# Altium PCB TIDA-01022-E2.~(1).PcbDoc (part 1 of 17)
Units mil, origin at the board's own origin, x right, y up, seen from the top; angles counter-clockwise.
Board outline 6929.13 x 11614.17 mil, 12 copper layers (L1_Top Layer, L2_GND, L3_GND, L4_Signal Layer 1, L5_GND, L6_PWR, L7_GND/PWR, L8_PWR, L9_GND/PWR, L10_Signal Layer 2, L11_GND, L12_Bottom Layer), stack 64.6 mil thick; 1711 components, 1001 nets, 5985 pads, 3200 vias.
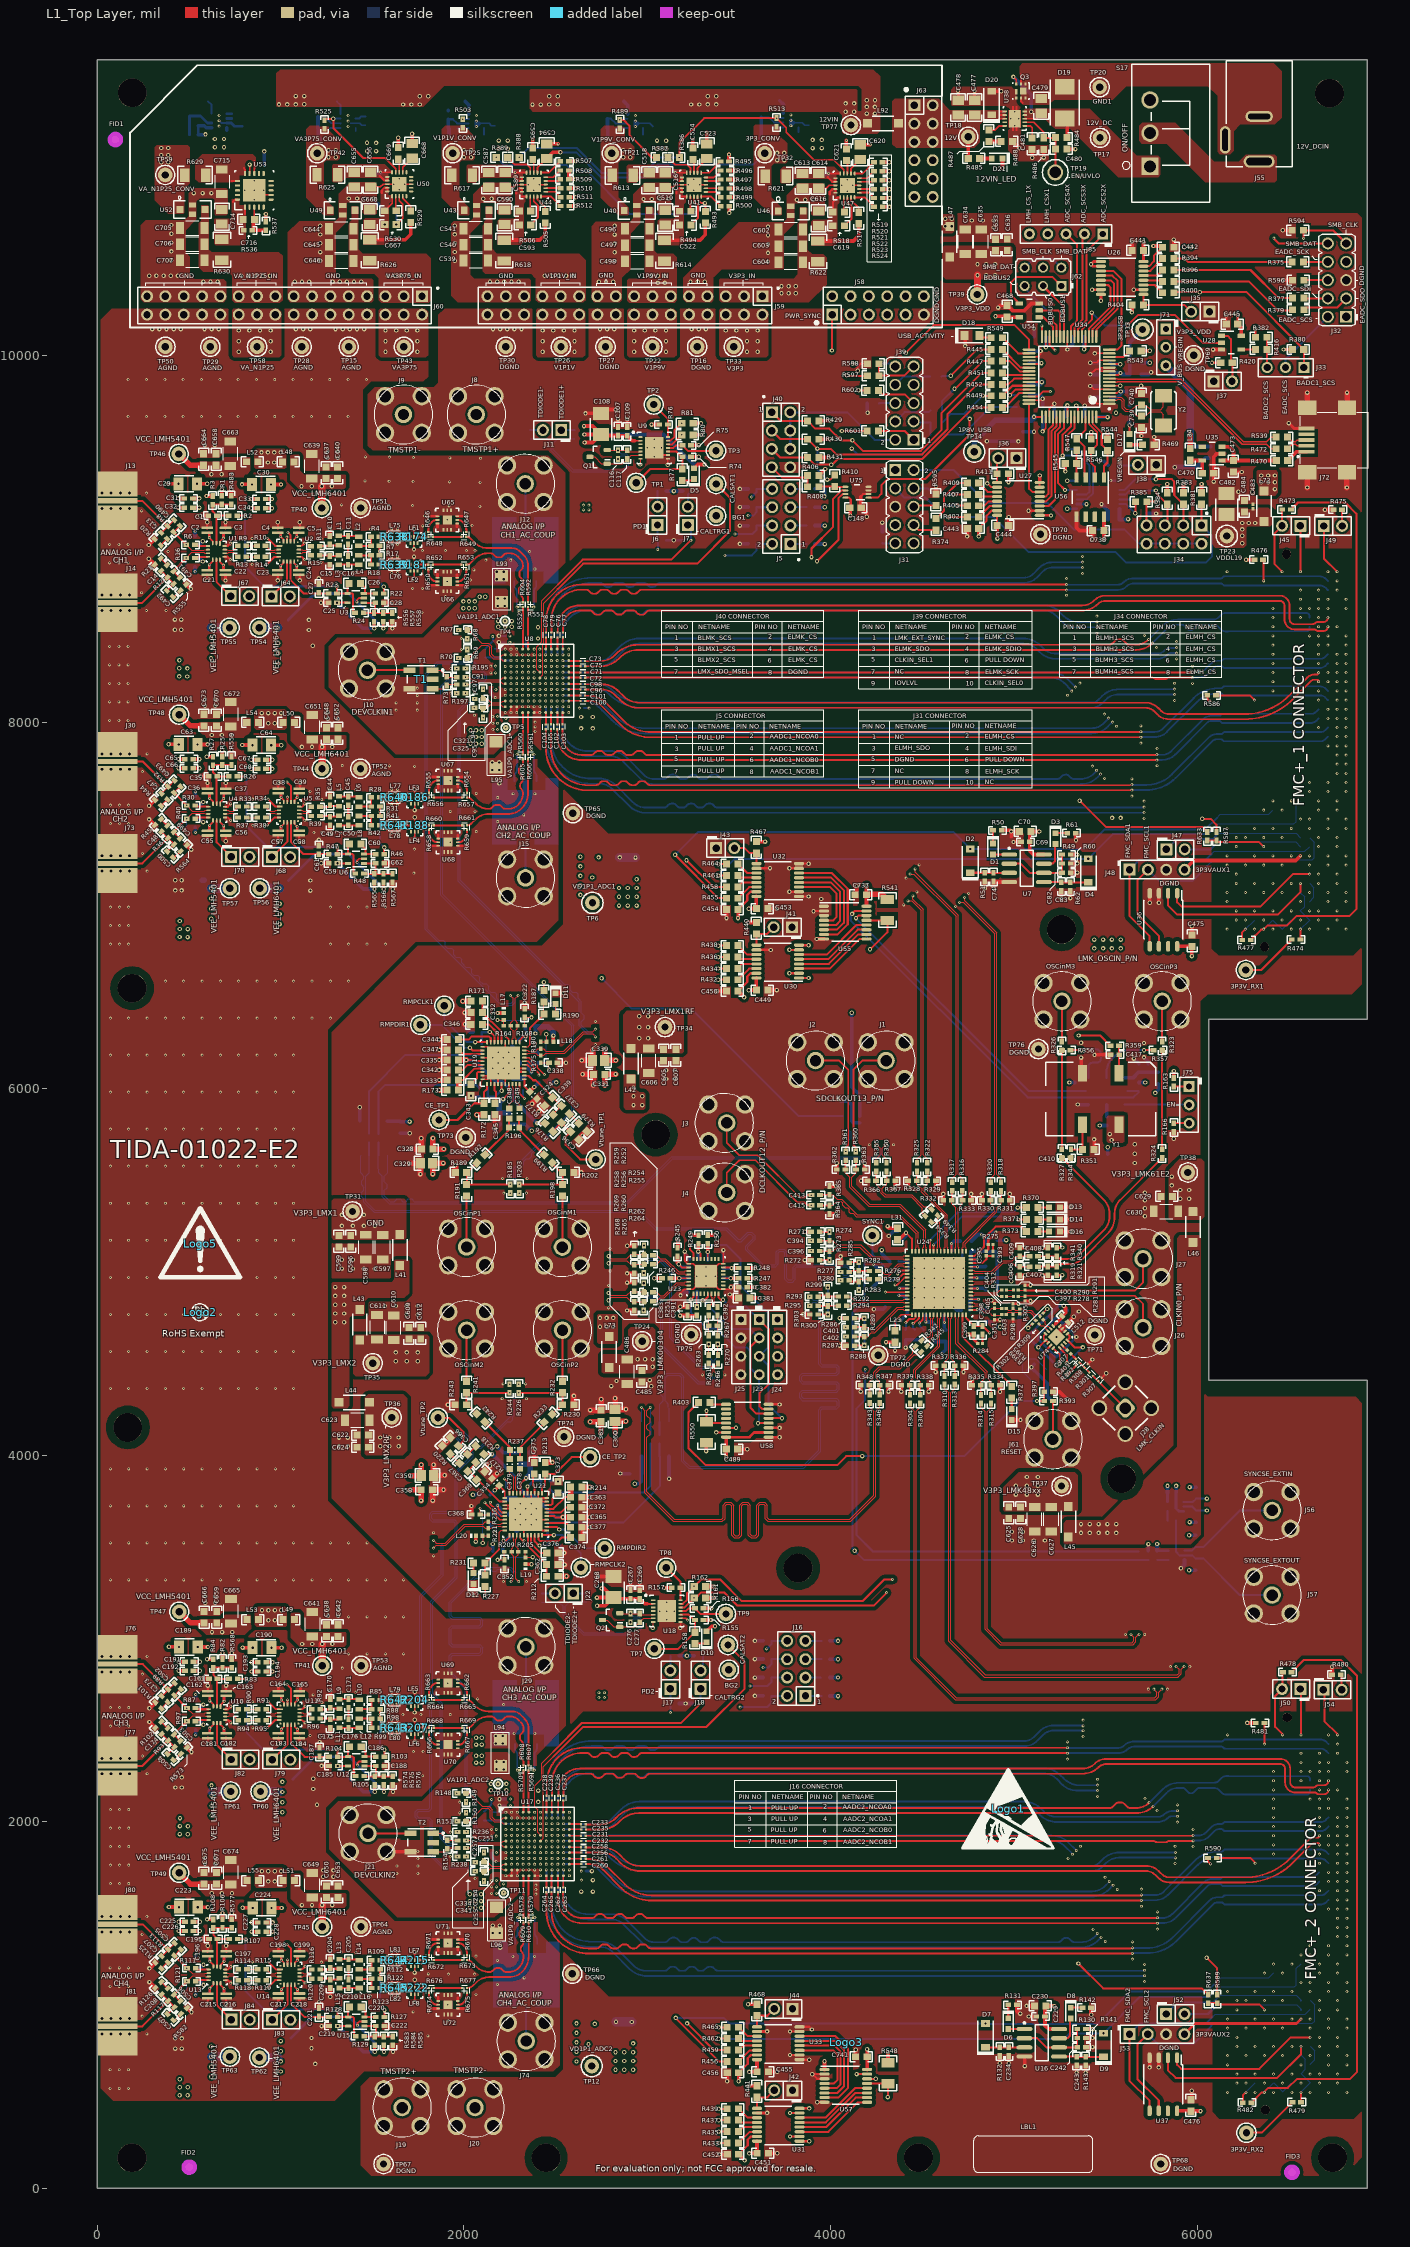
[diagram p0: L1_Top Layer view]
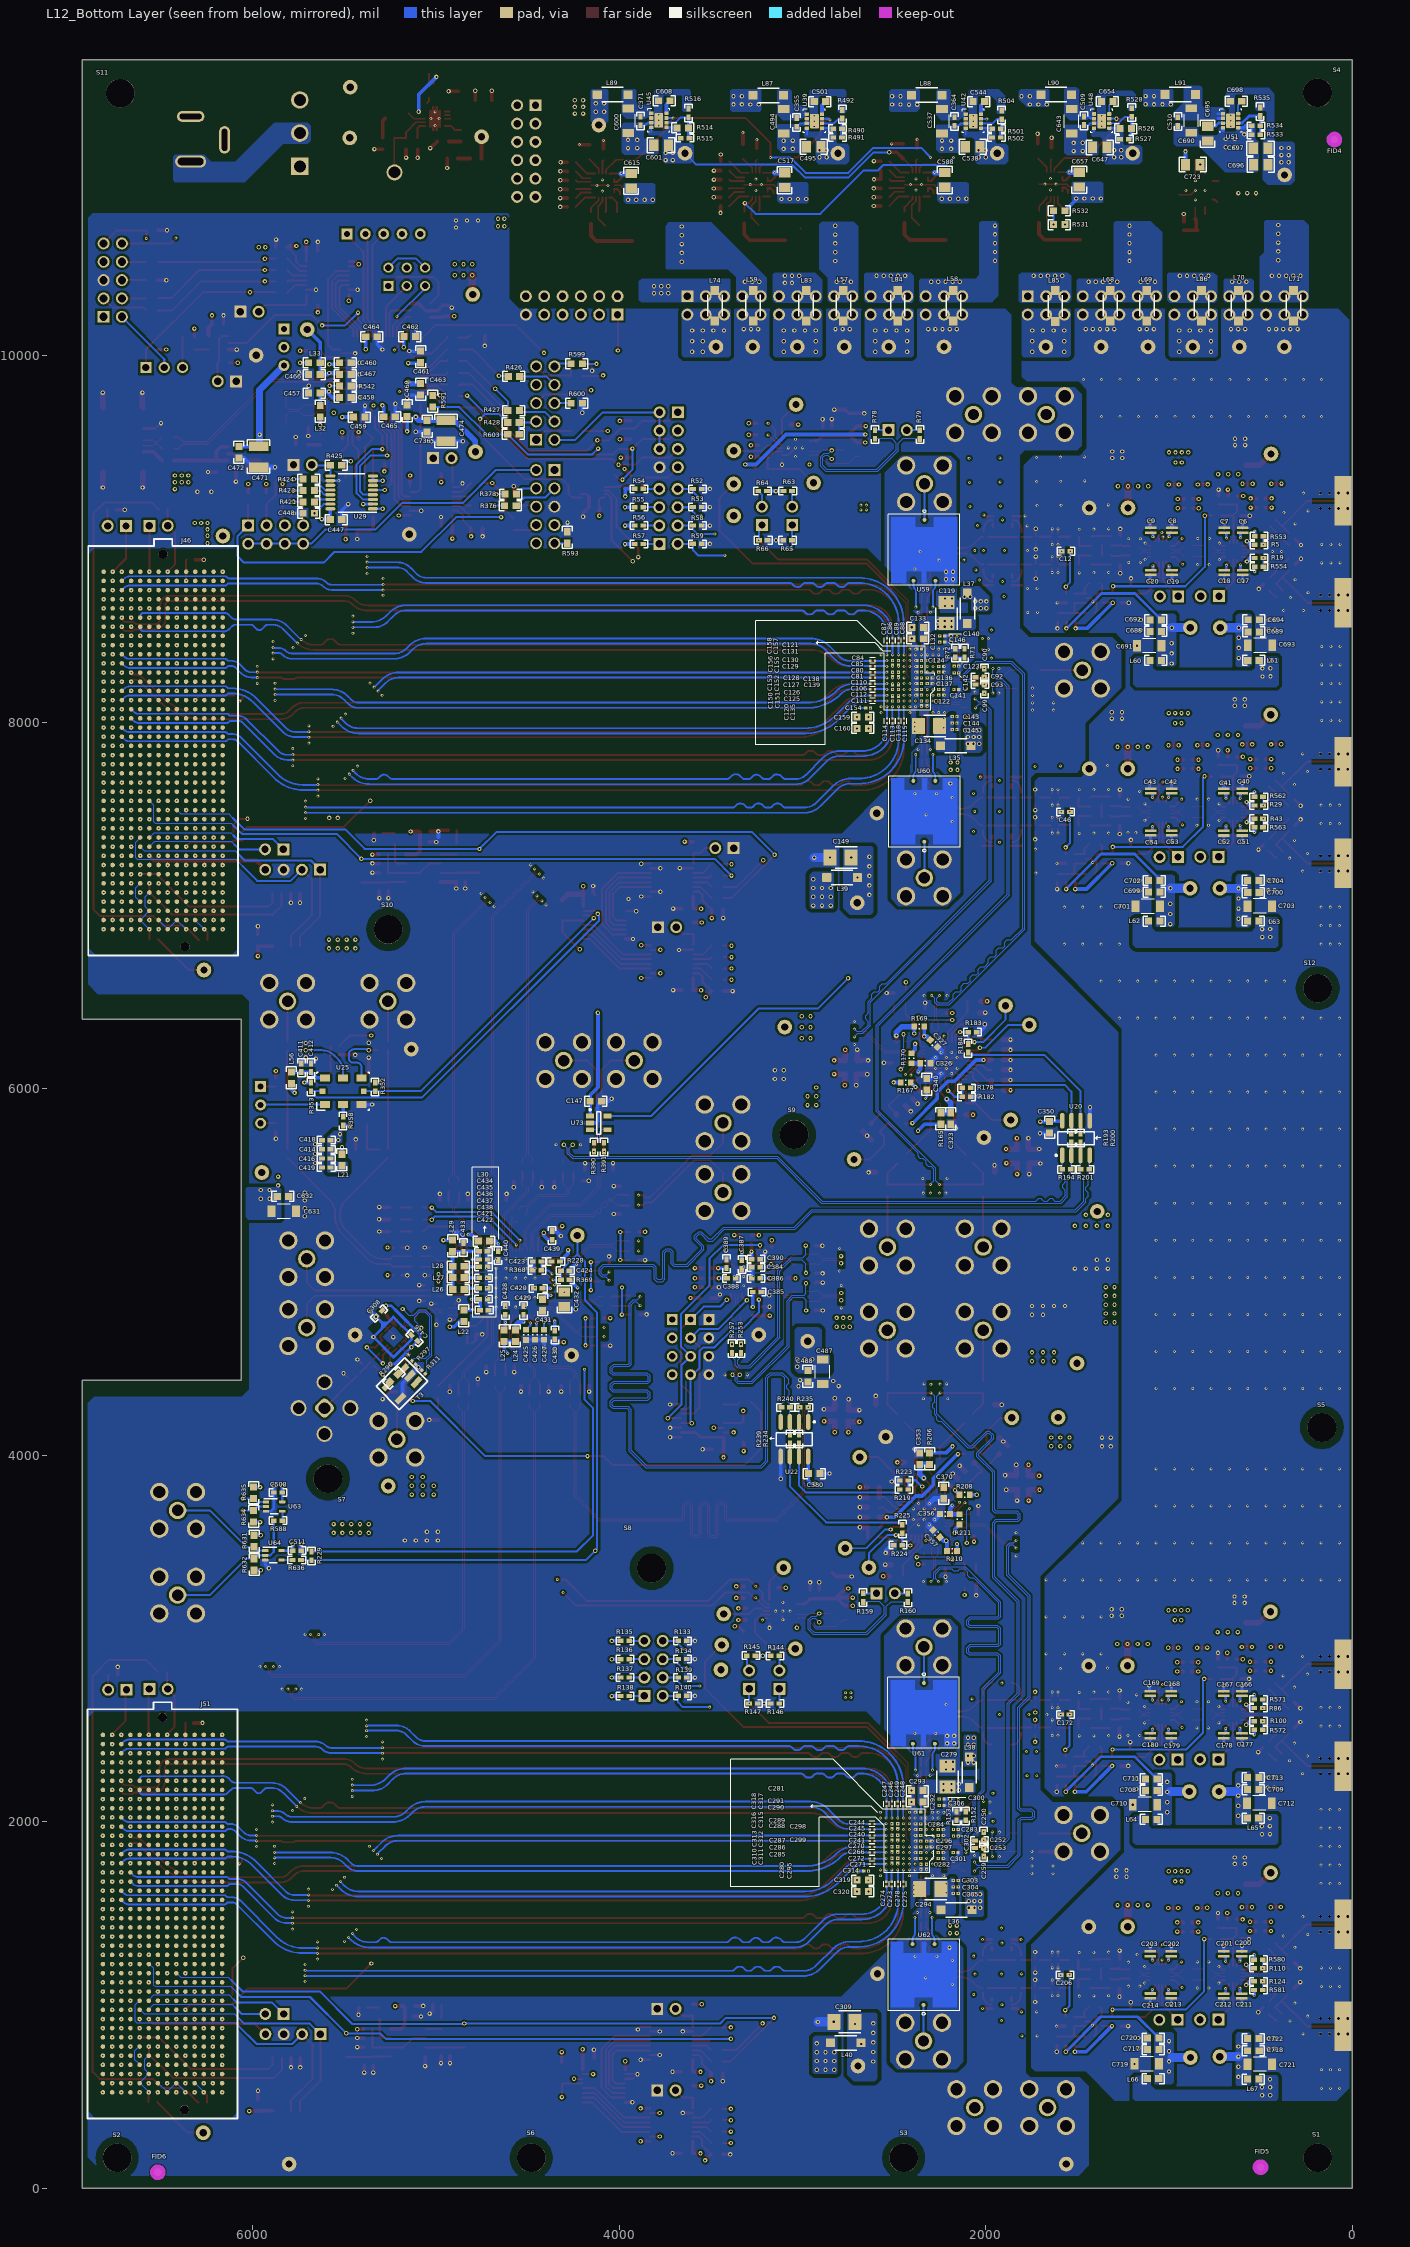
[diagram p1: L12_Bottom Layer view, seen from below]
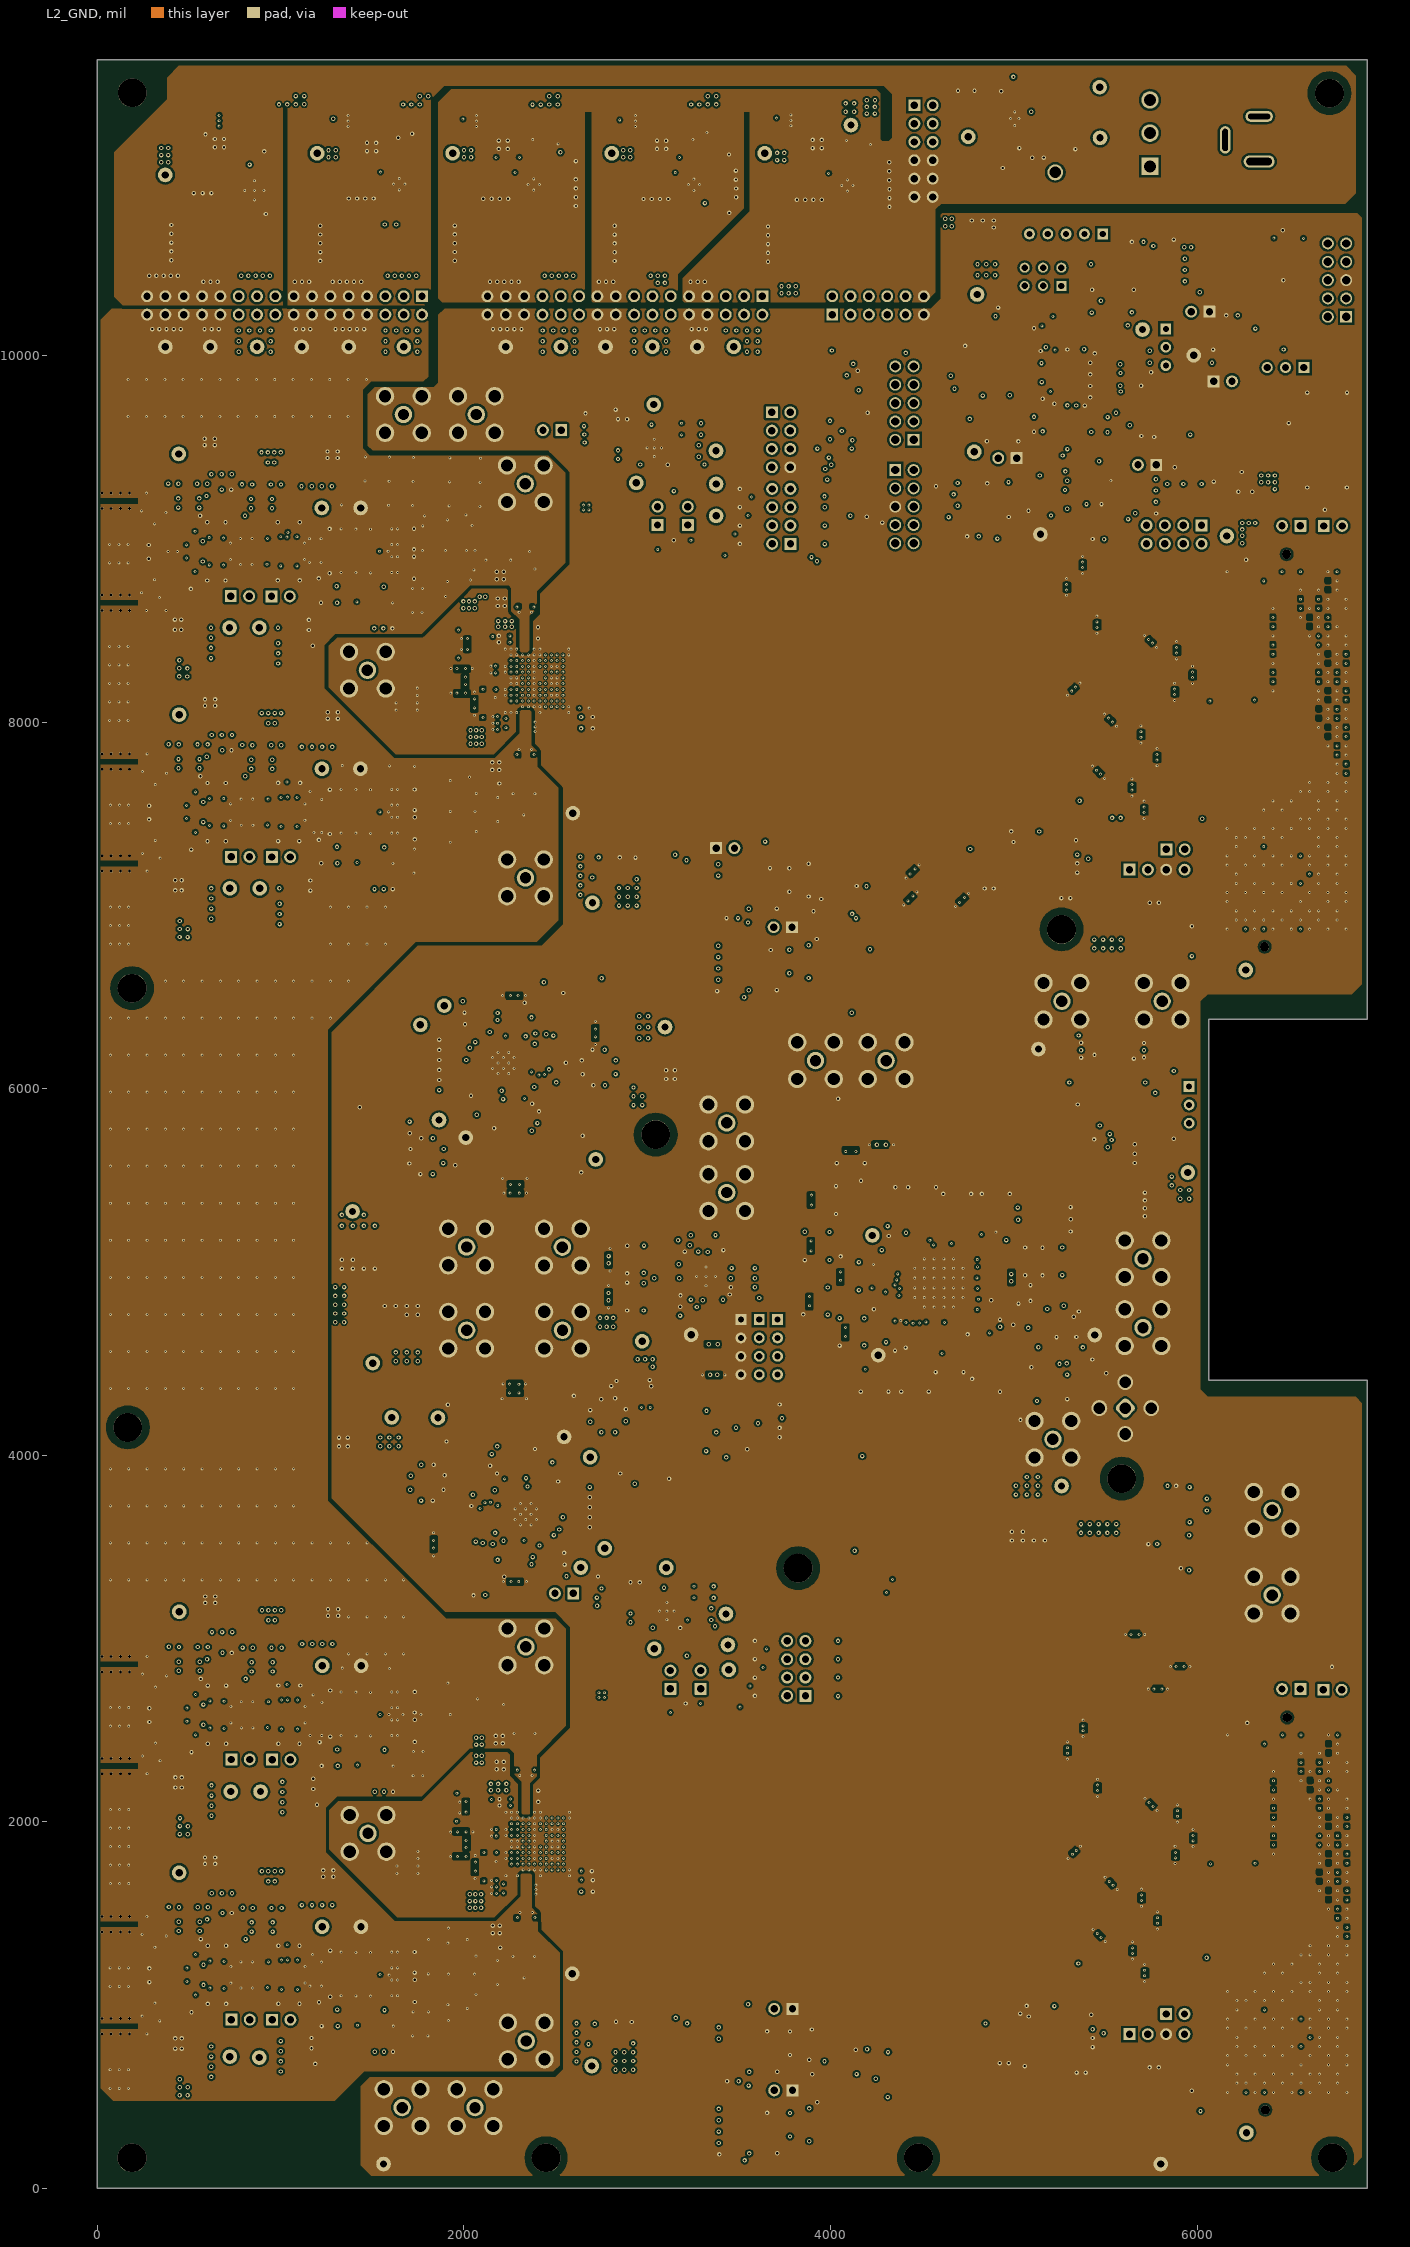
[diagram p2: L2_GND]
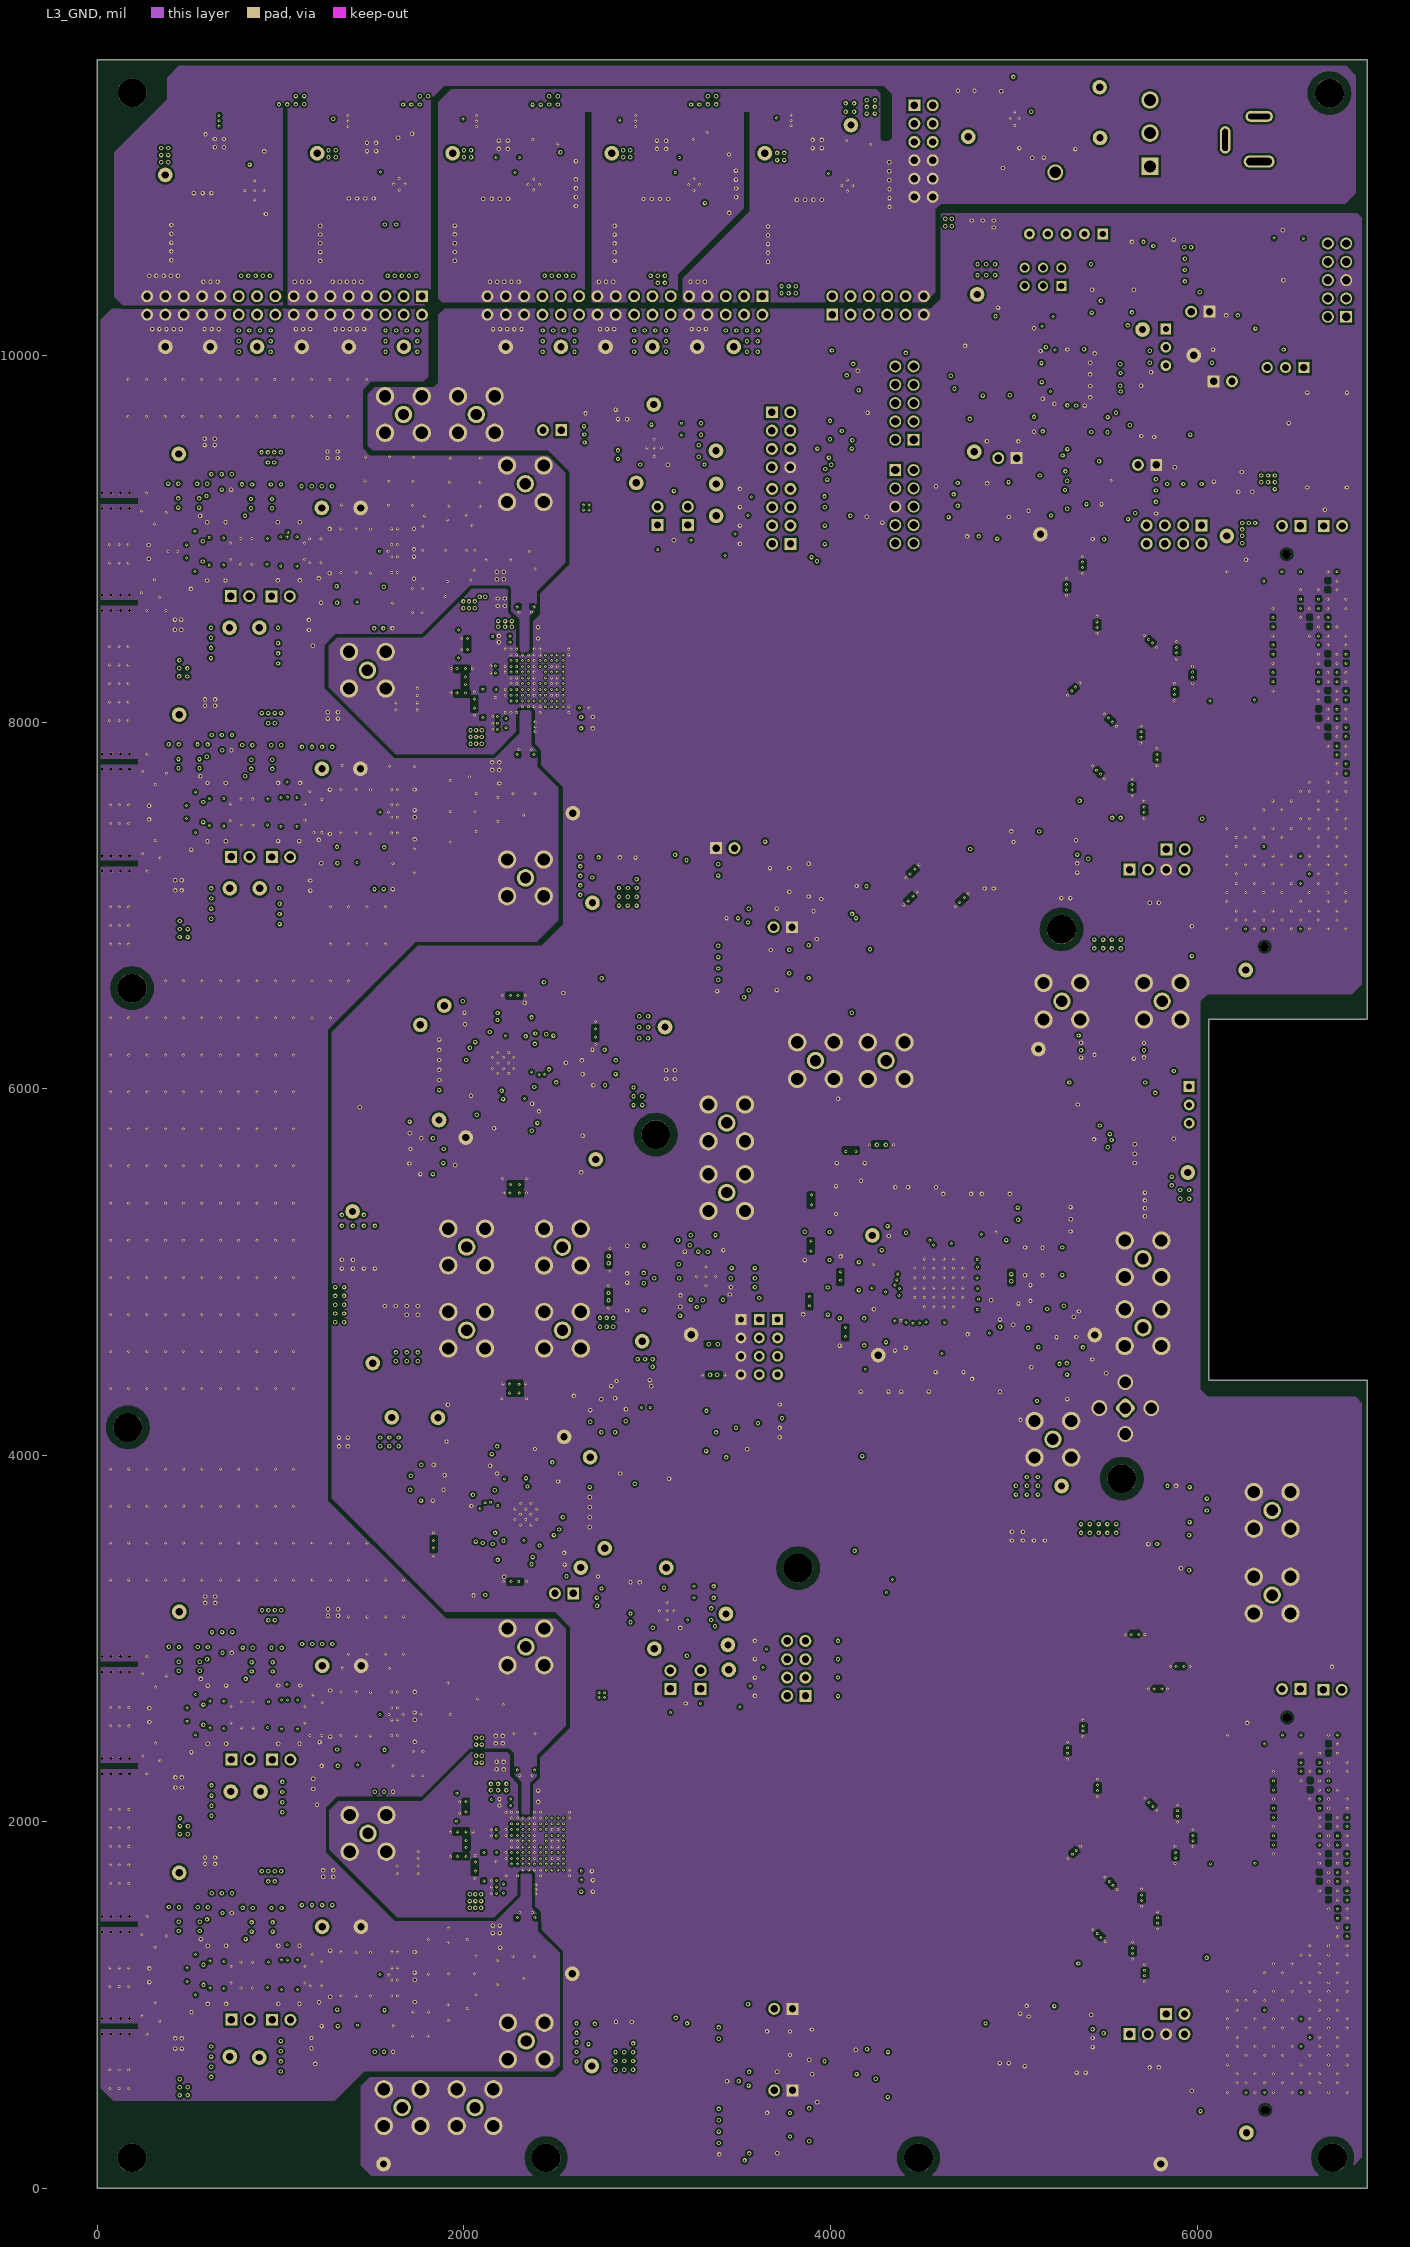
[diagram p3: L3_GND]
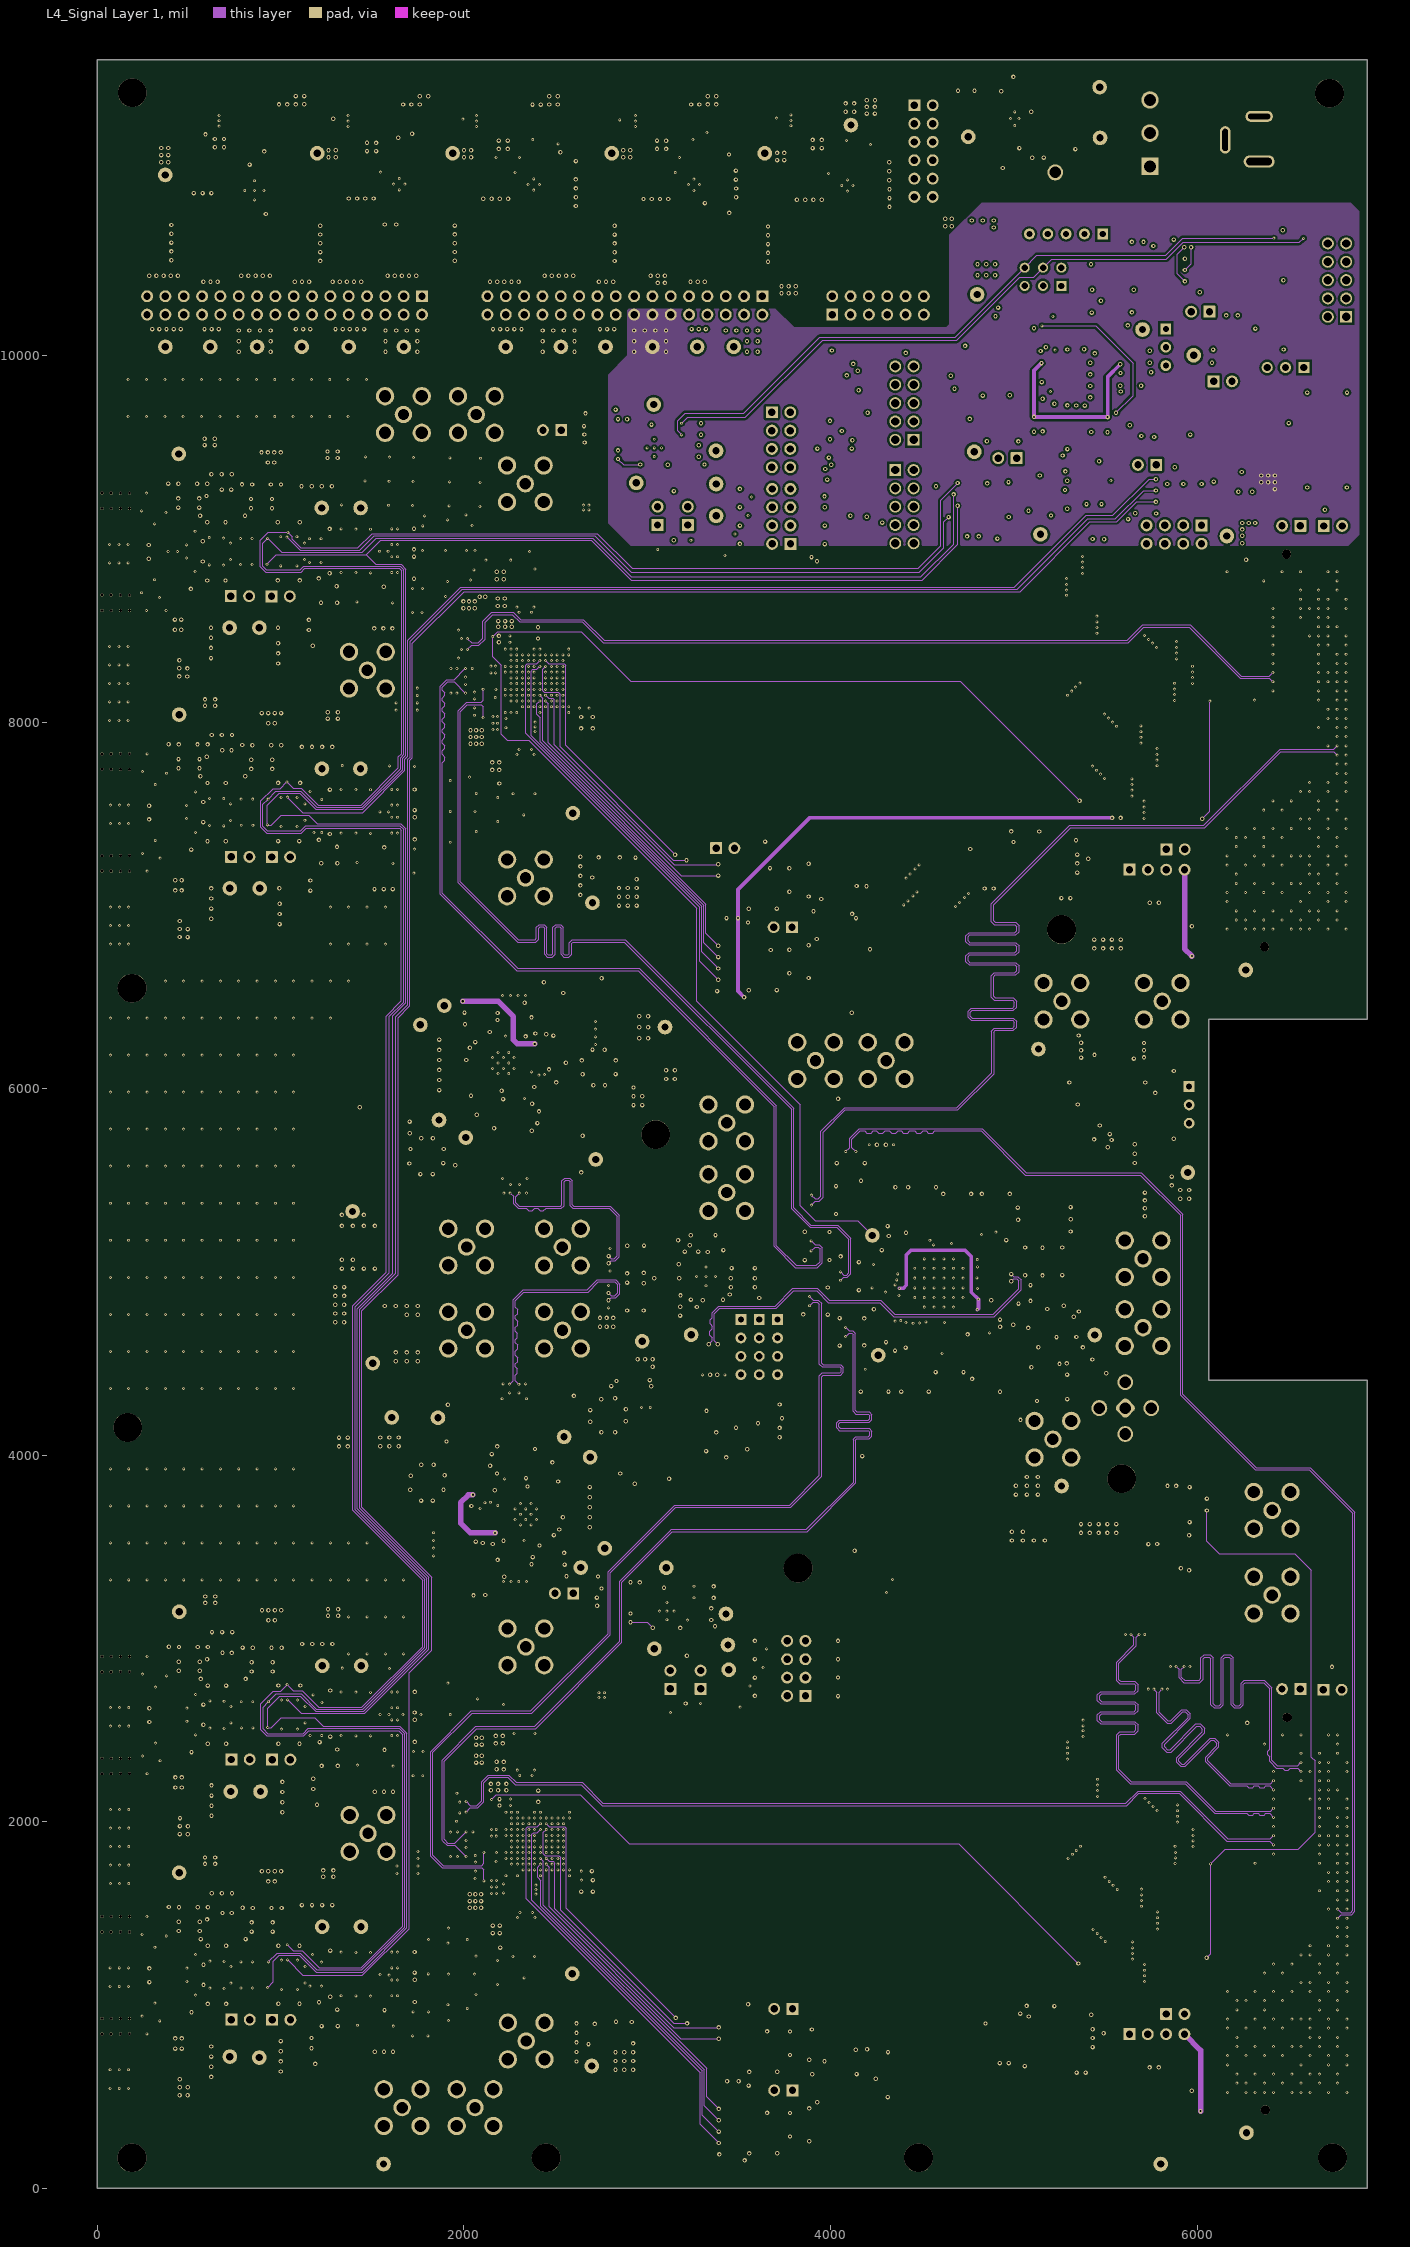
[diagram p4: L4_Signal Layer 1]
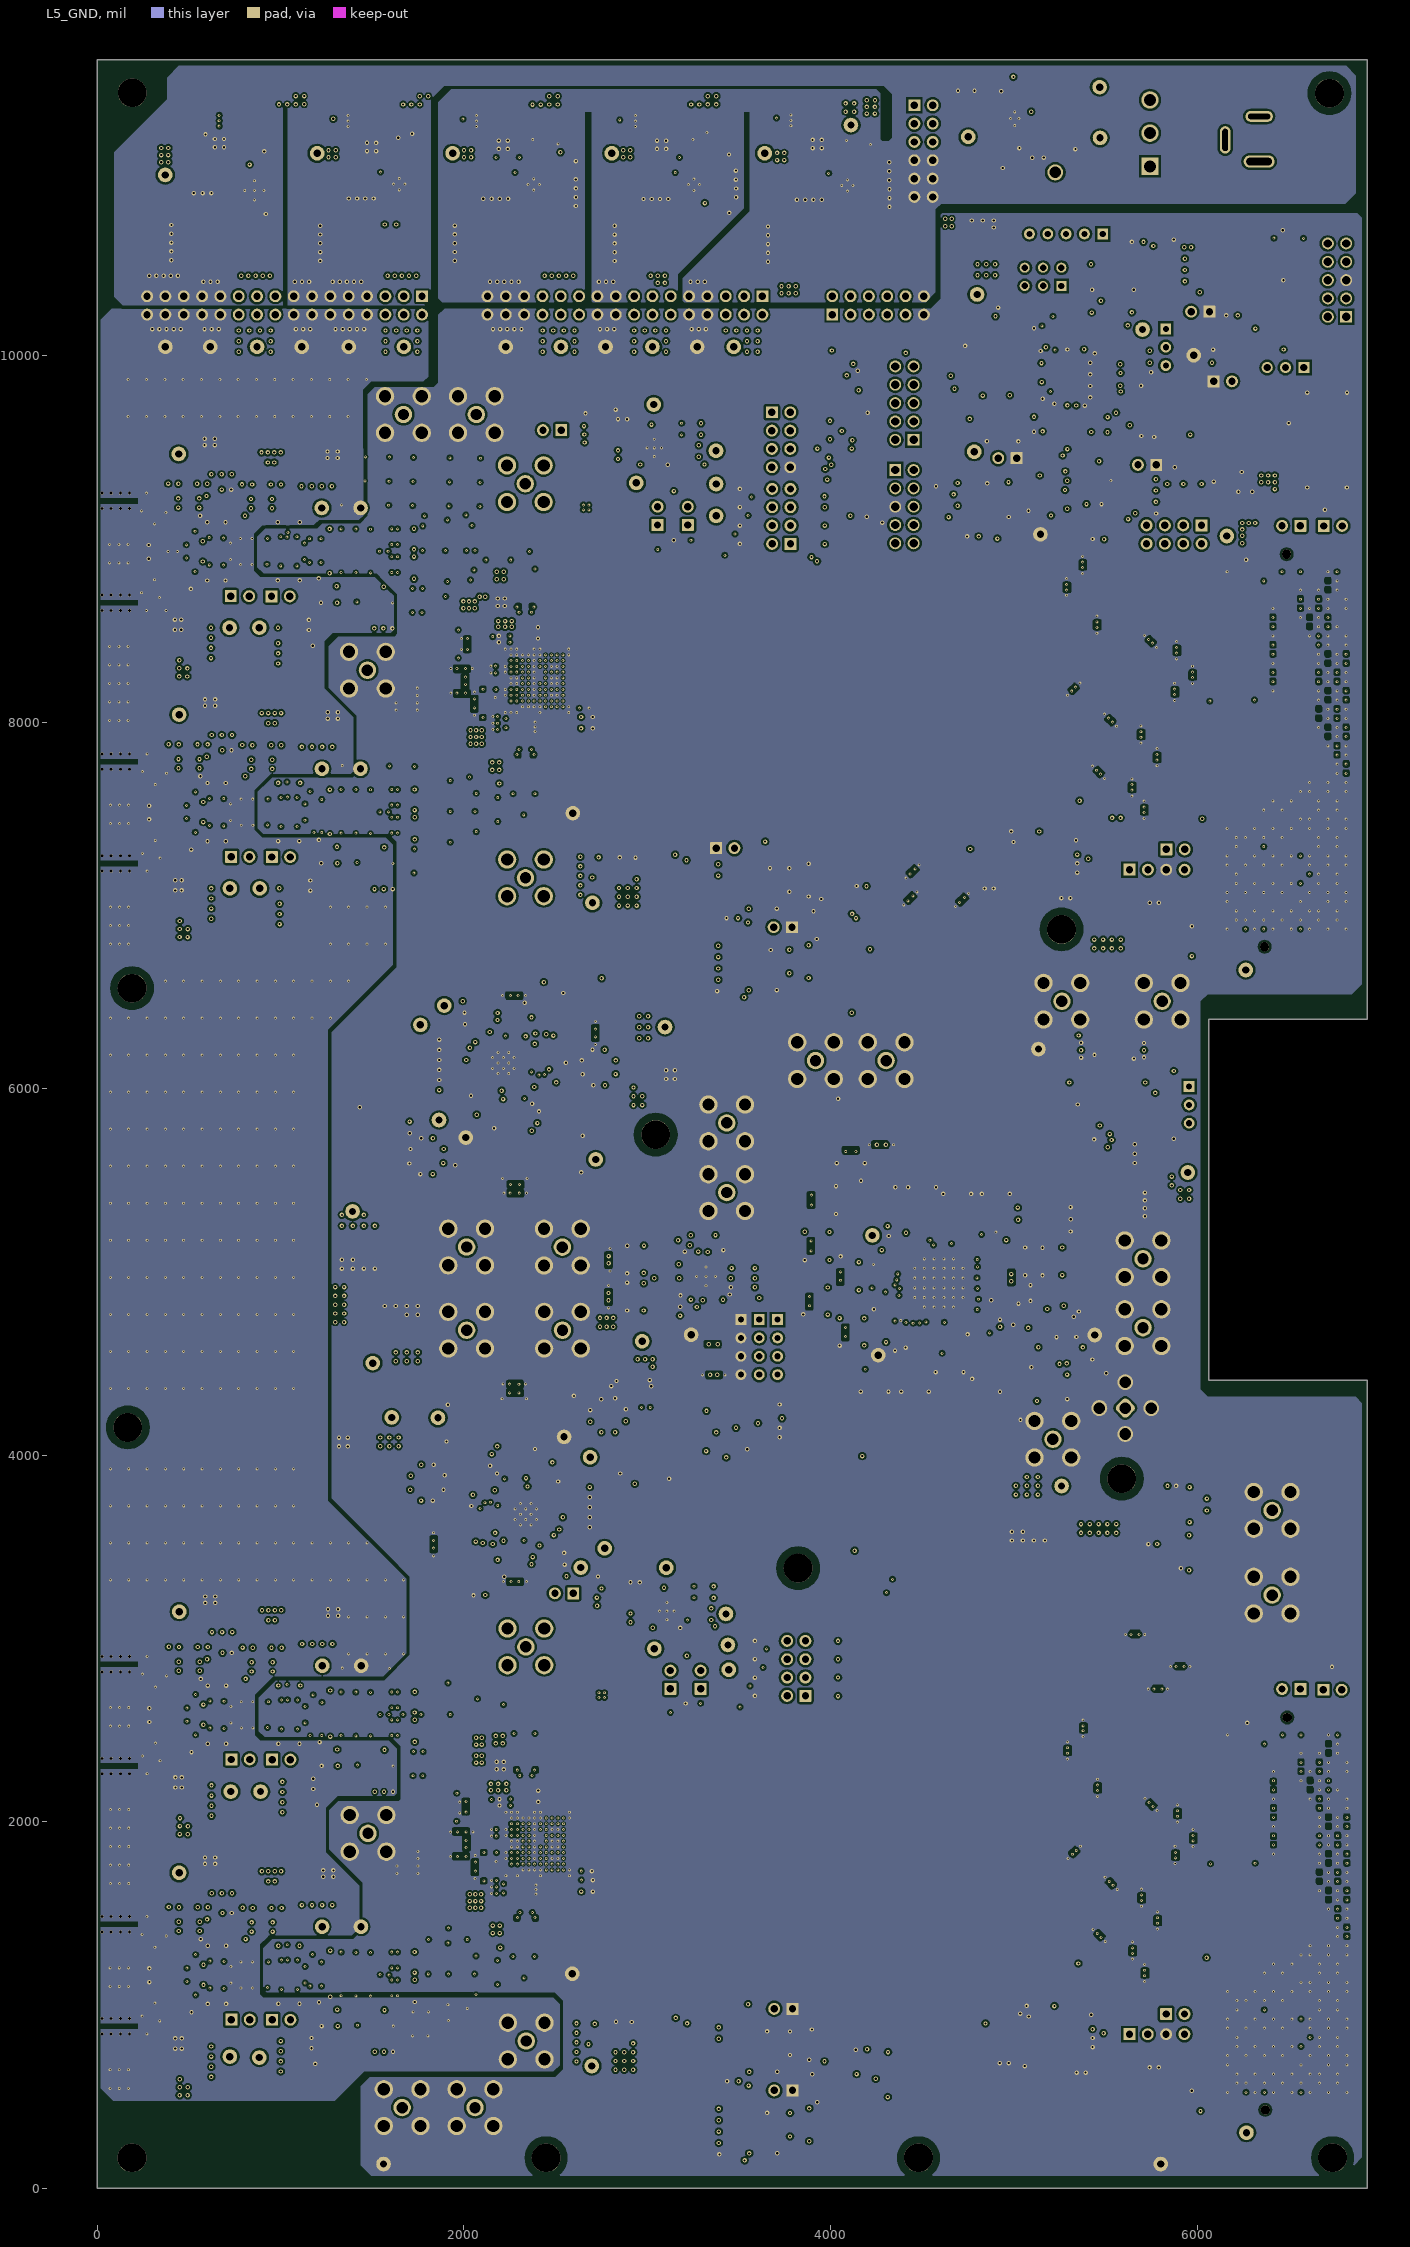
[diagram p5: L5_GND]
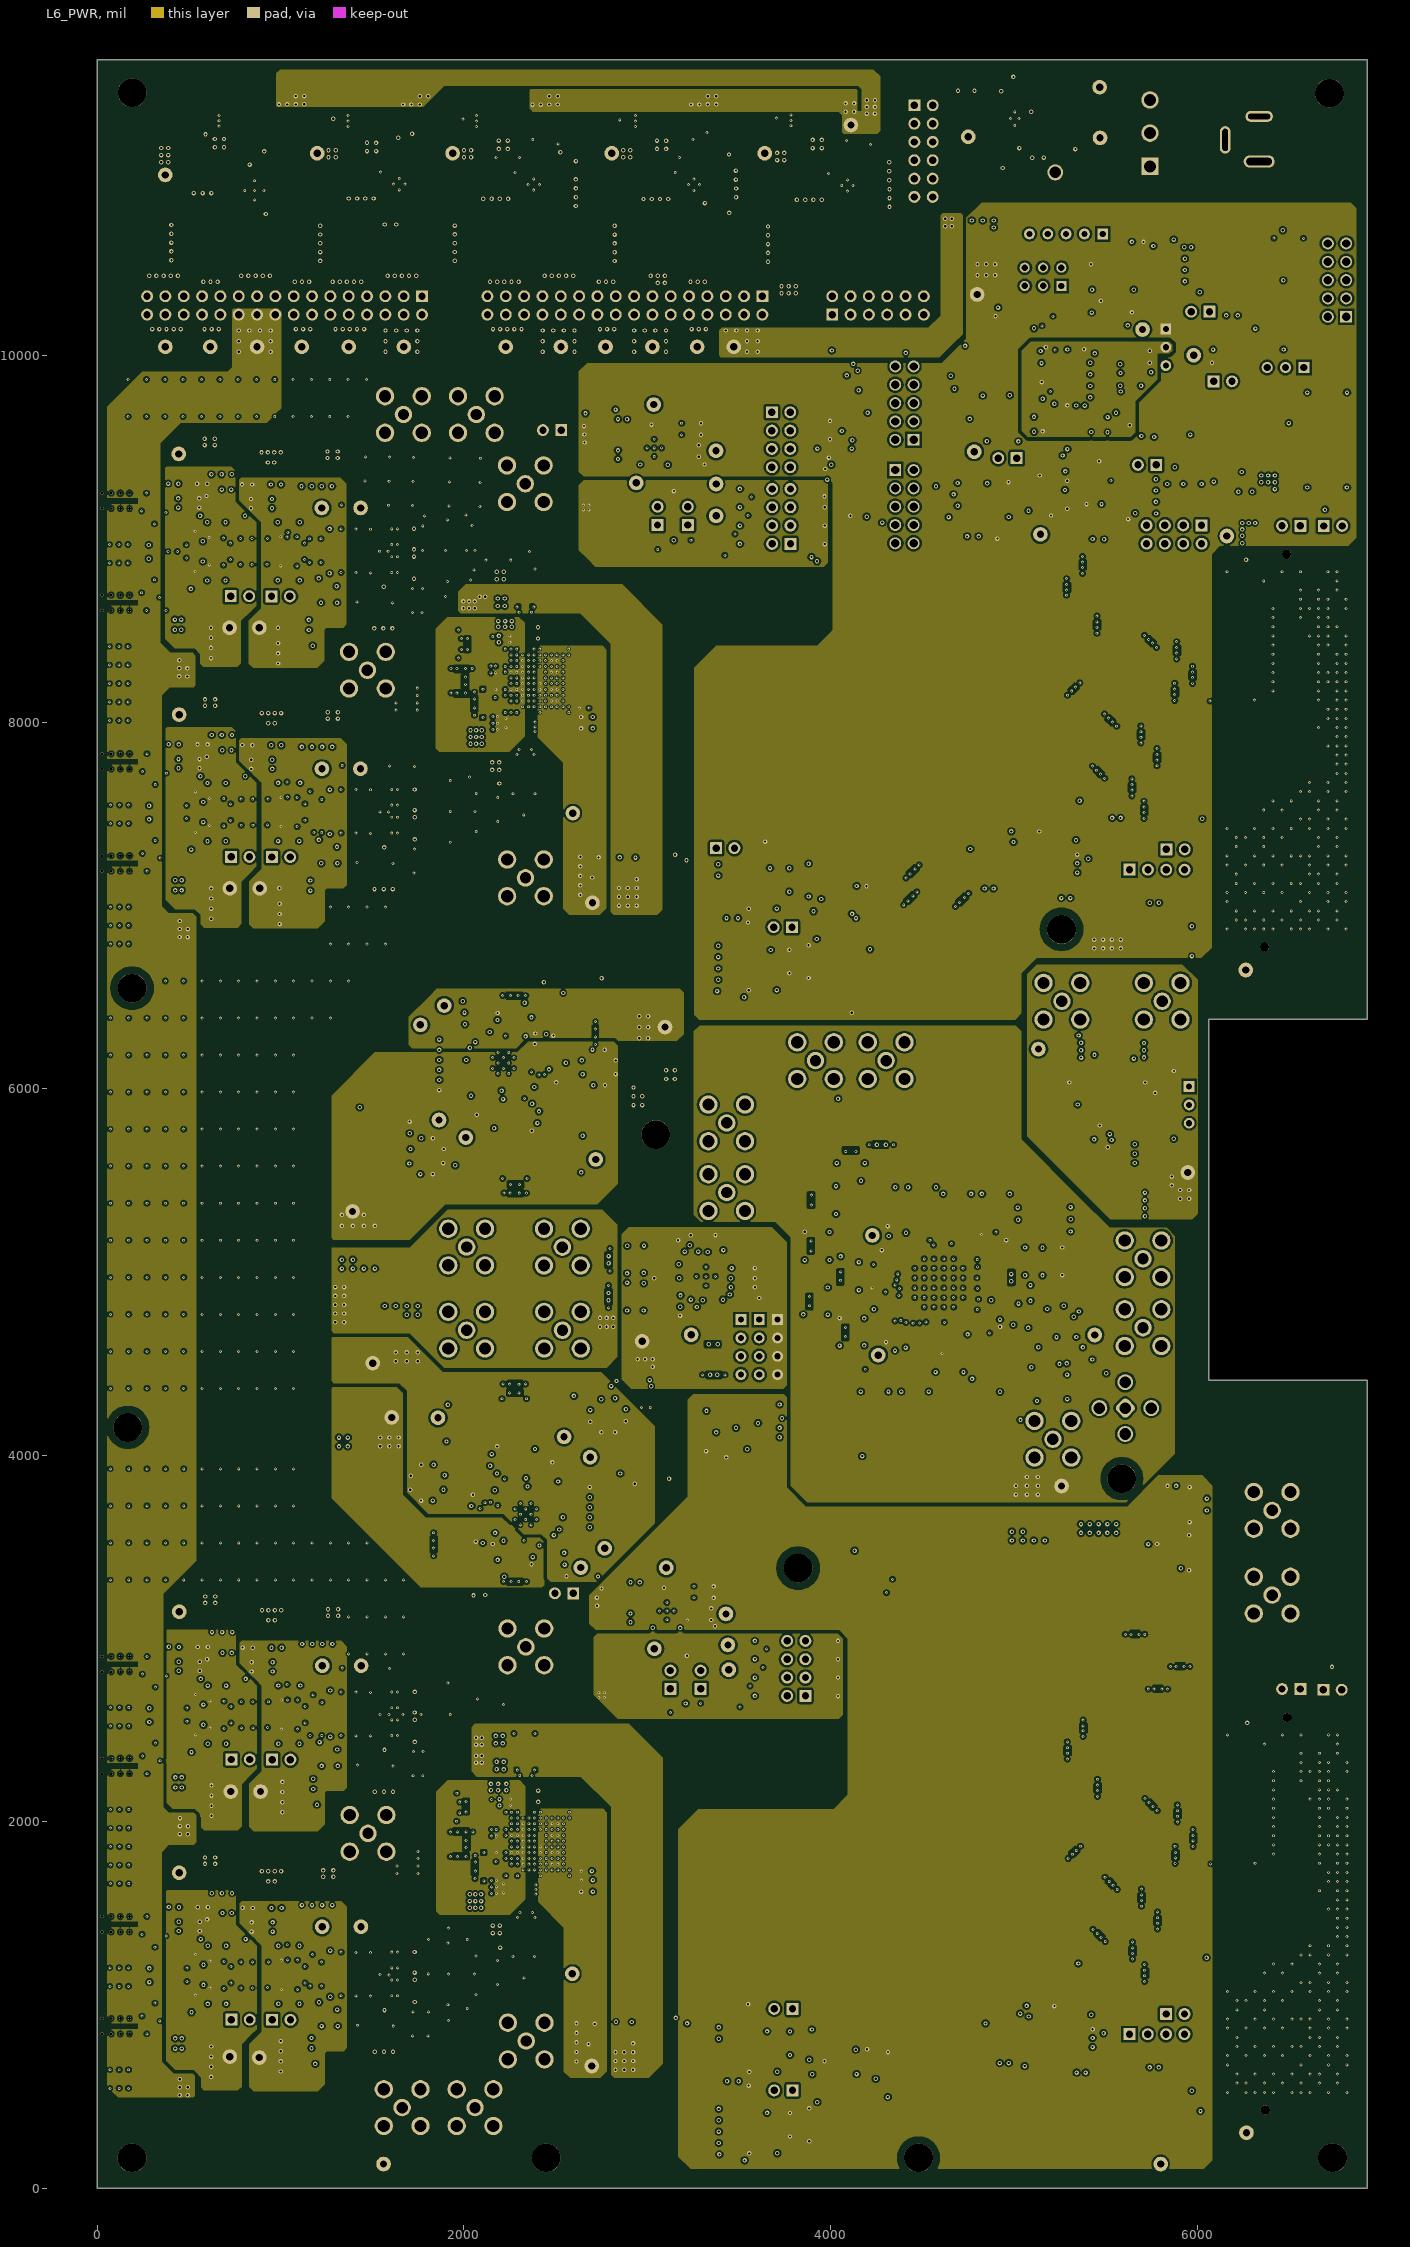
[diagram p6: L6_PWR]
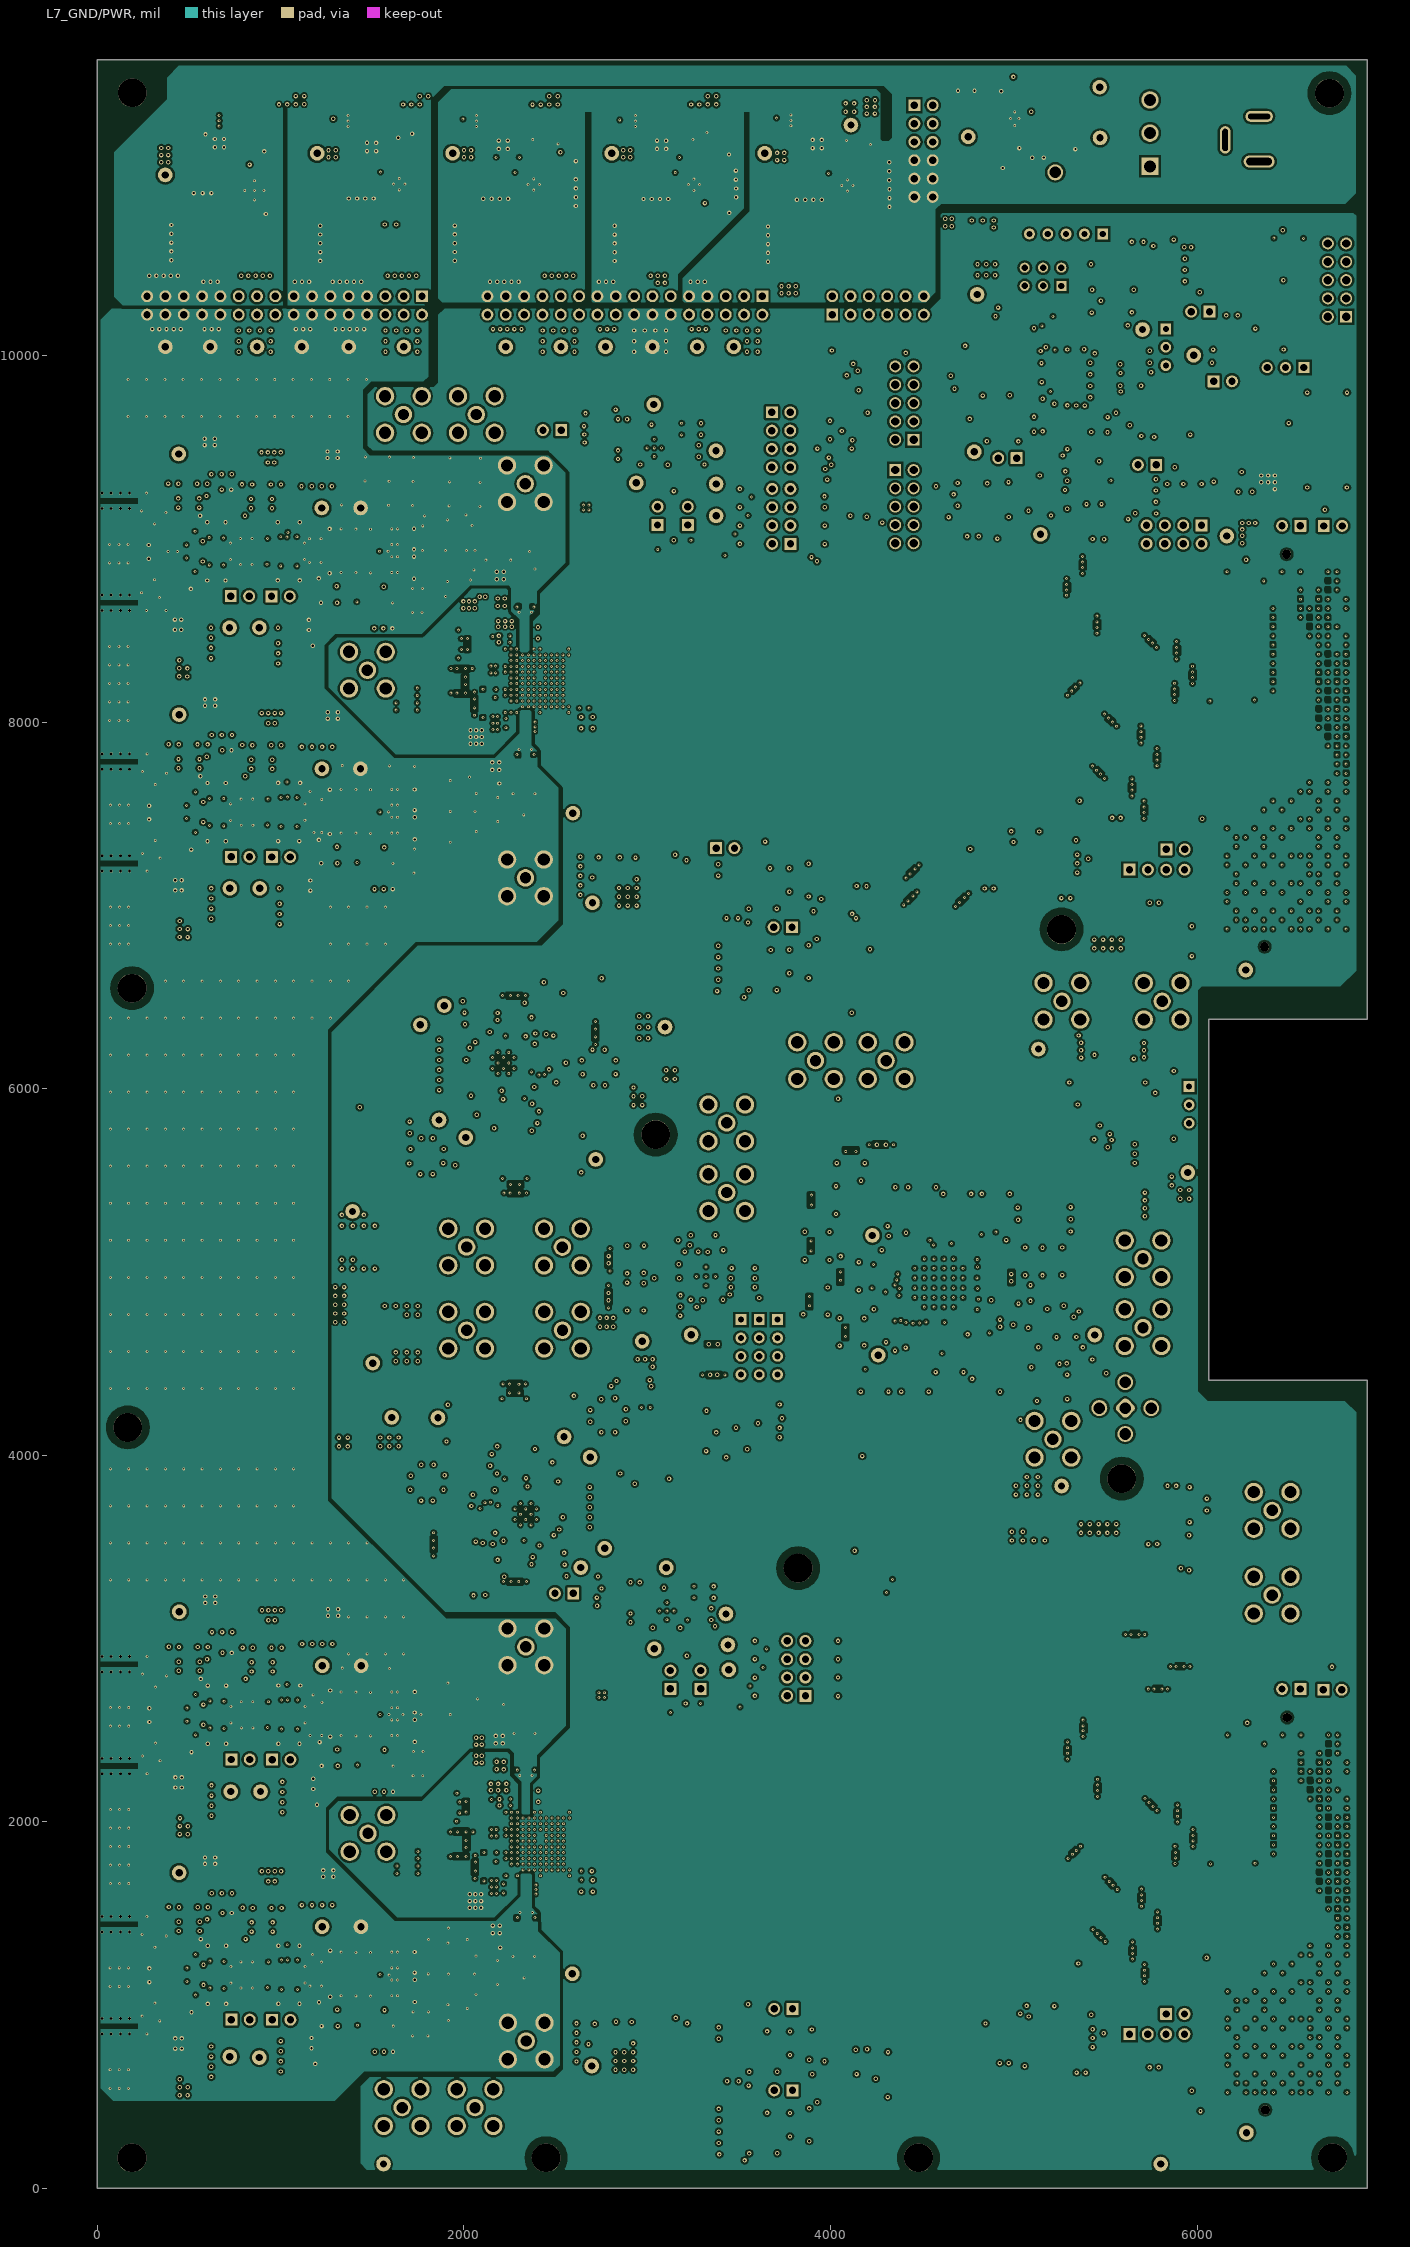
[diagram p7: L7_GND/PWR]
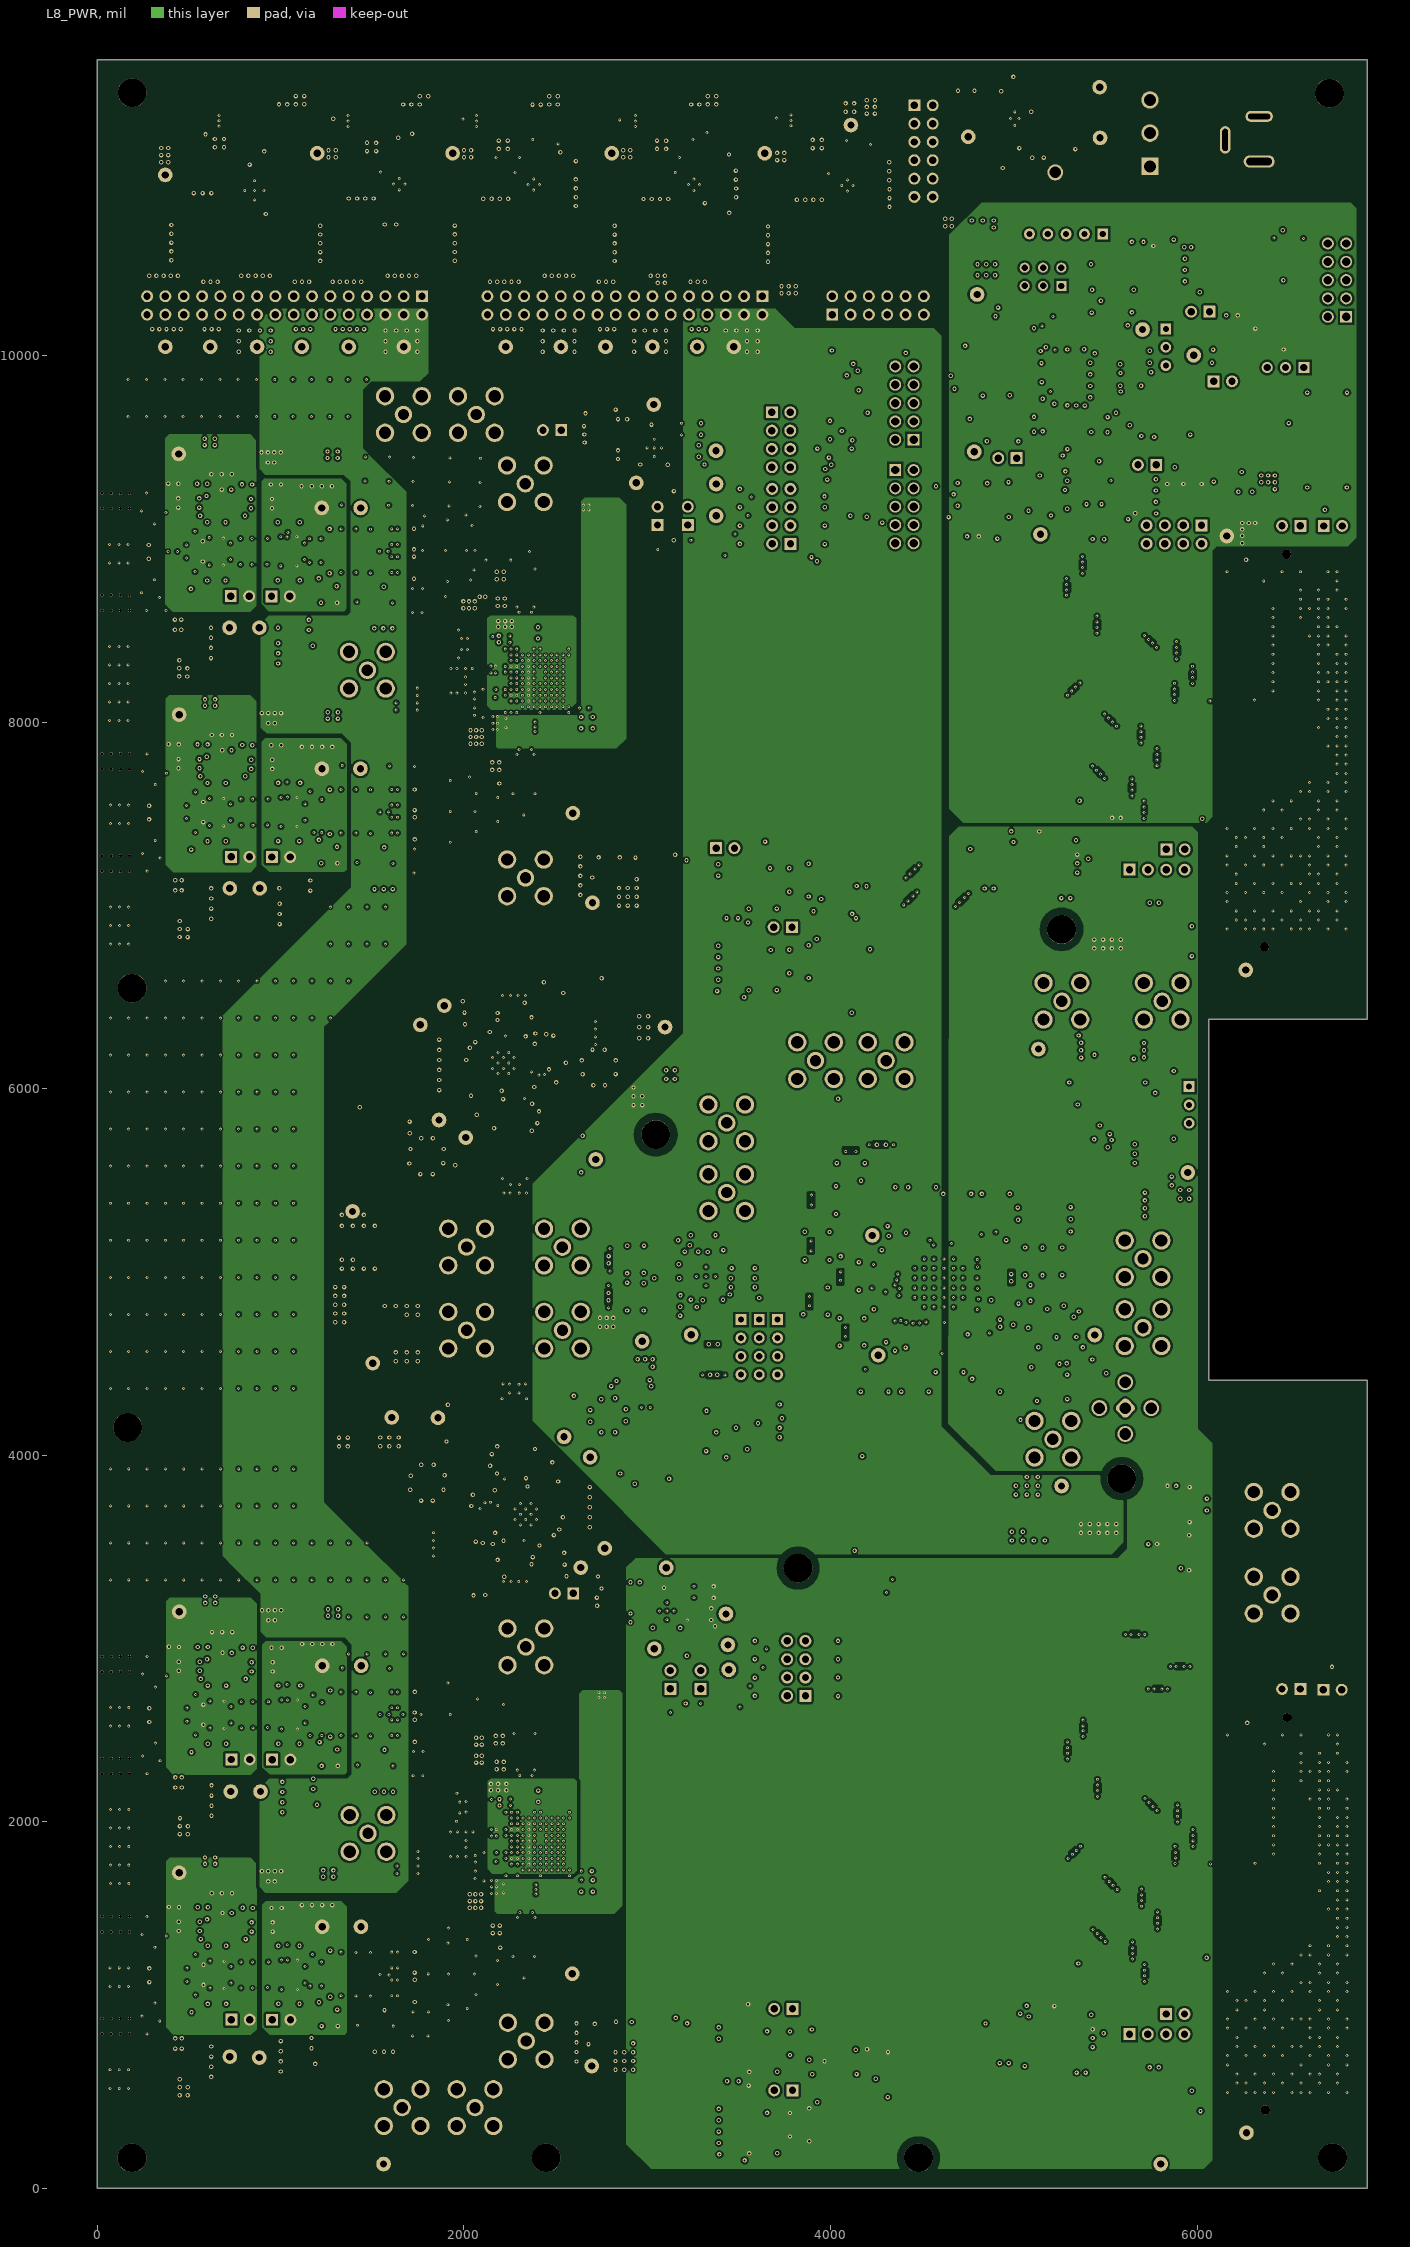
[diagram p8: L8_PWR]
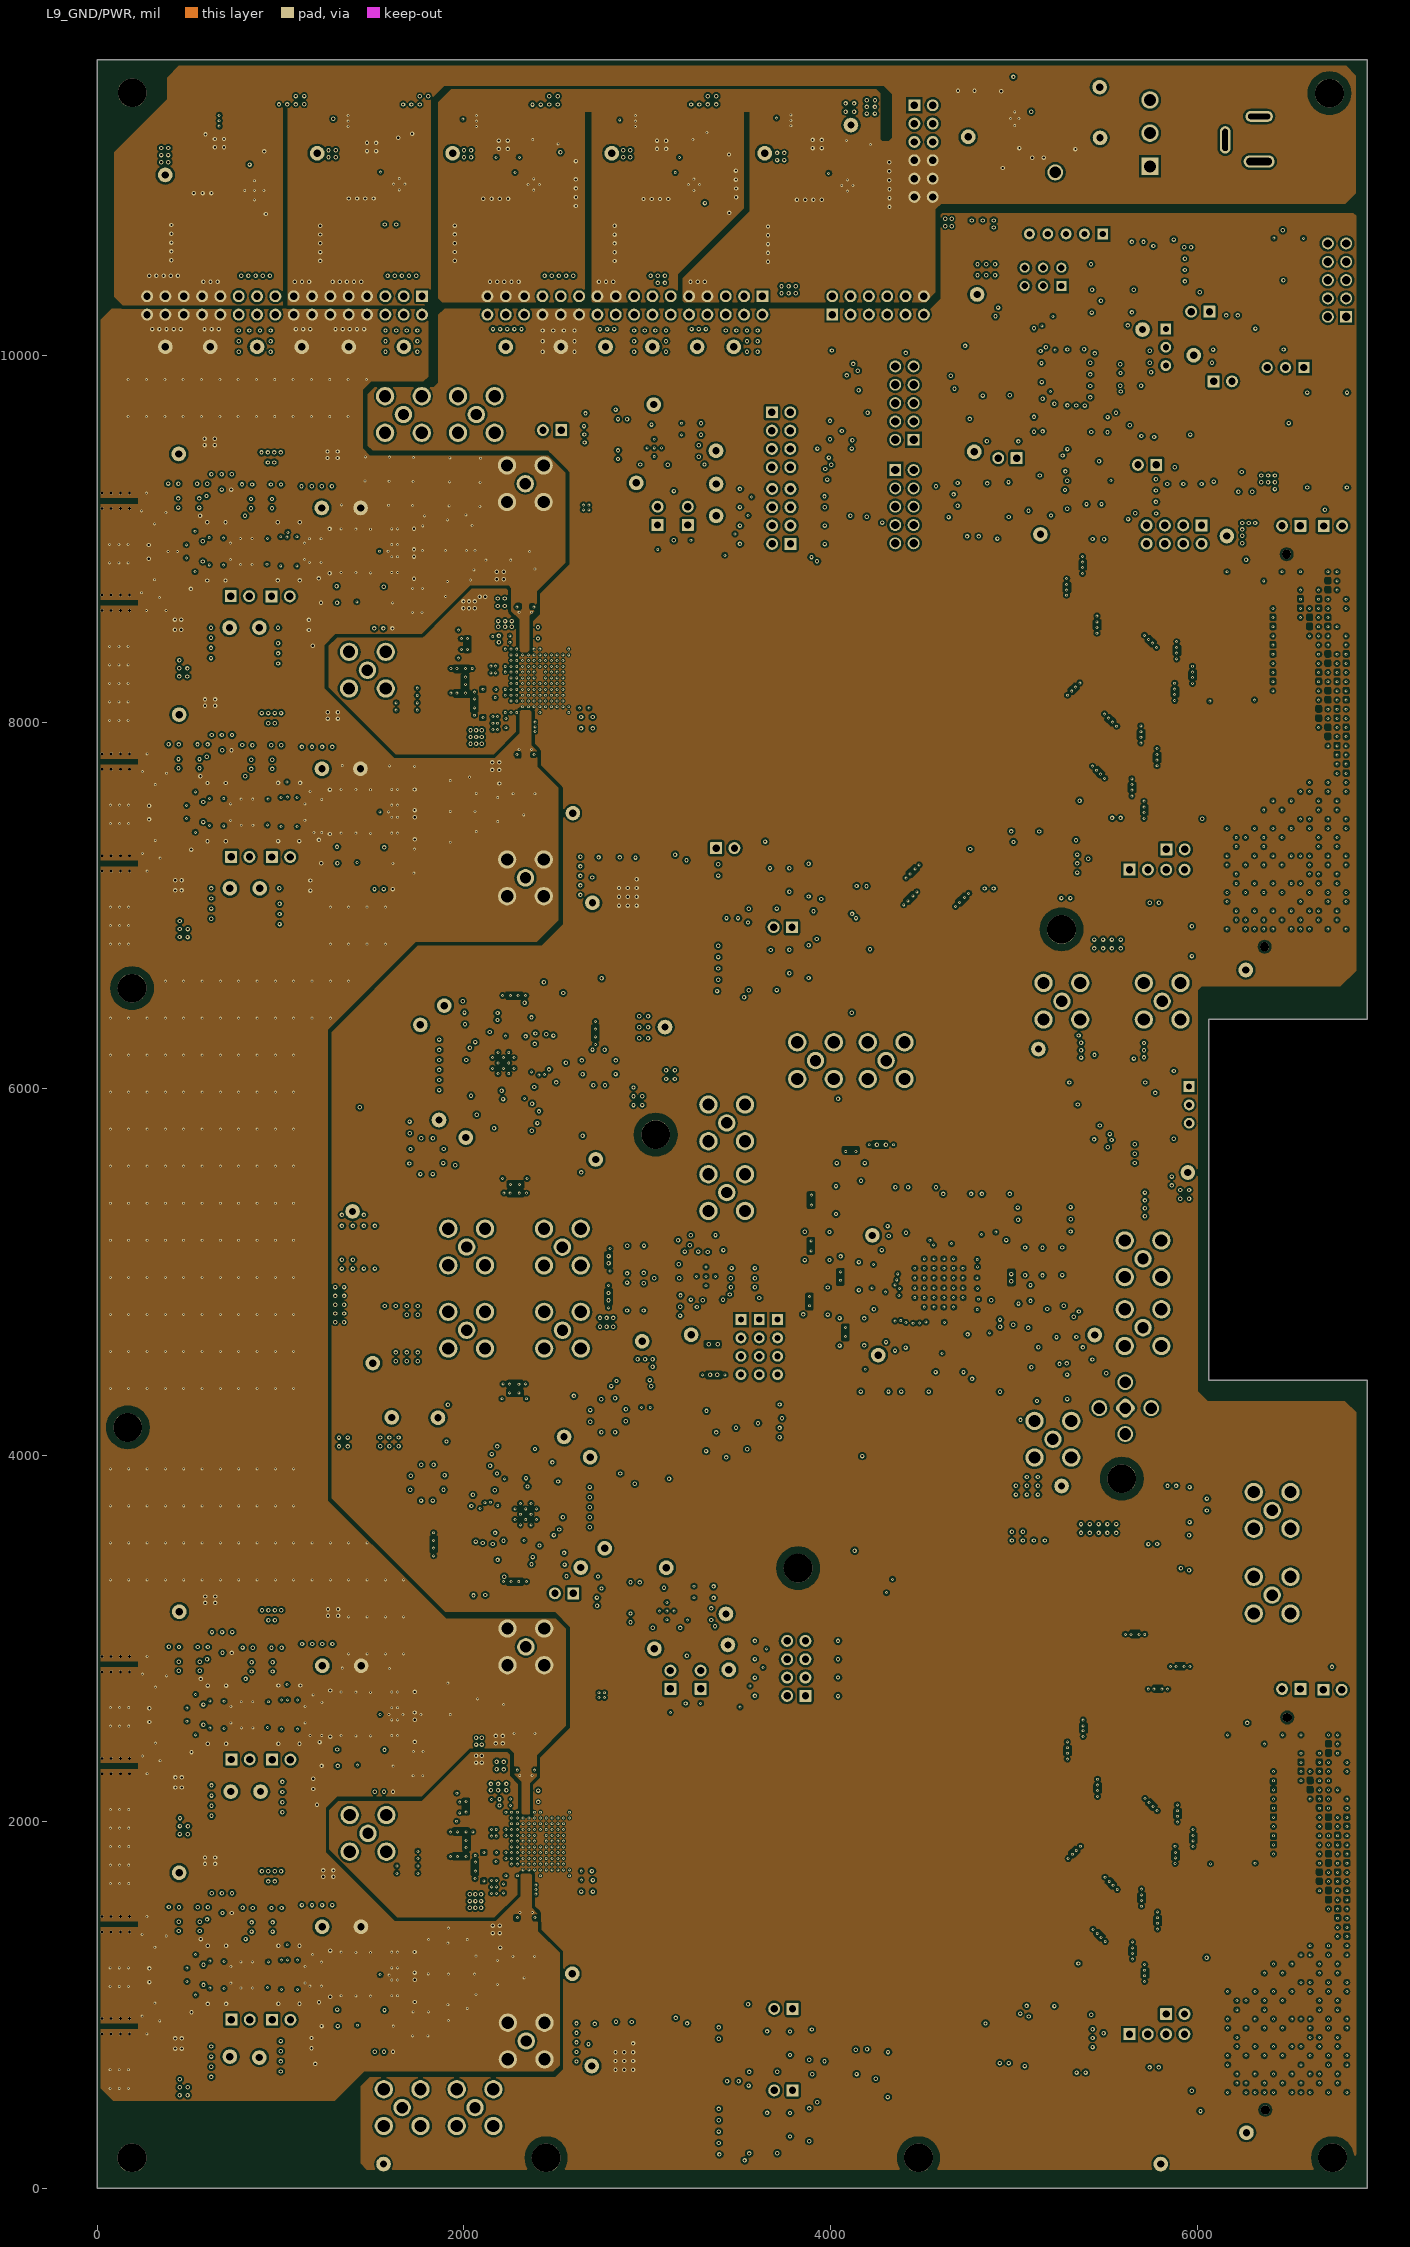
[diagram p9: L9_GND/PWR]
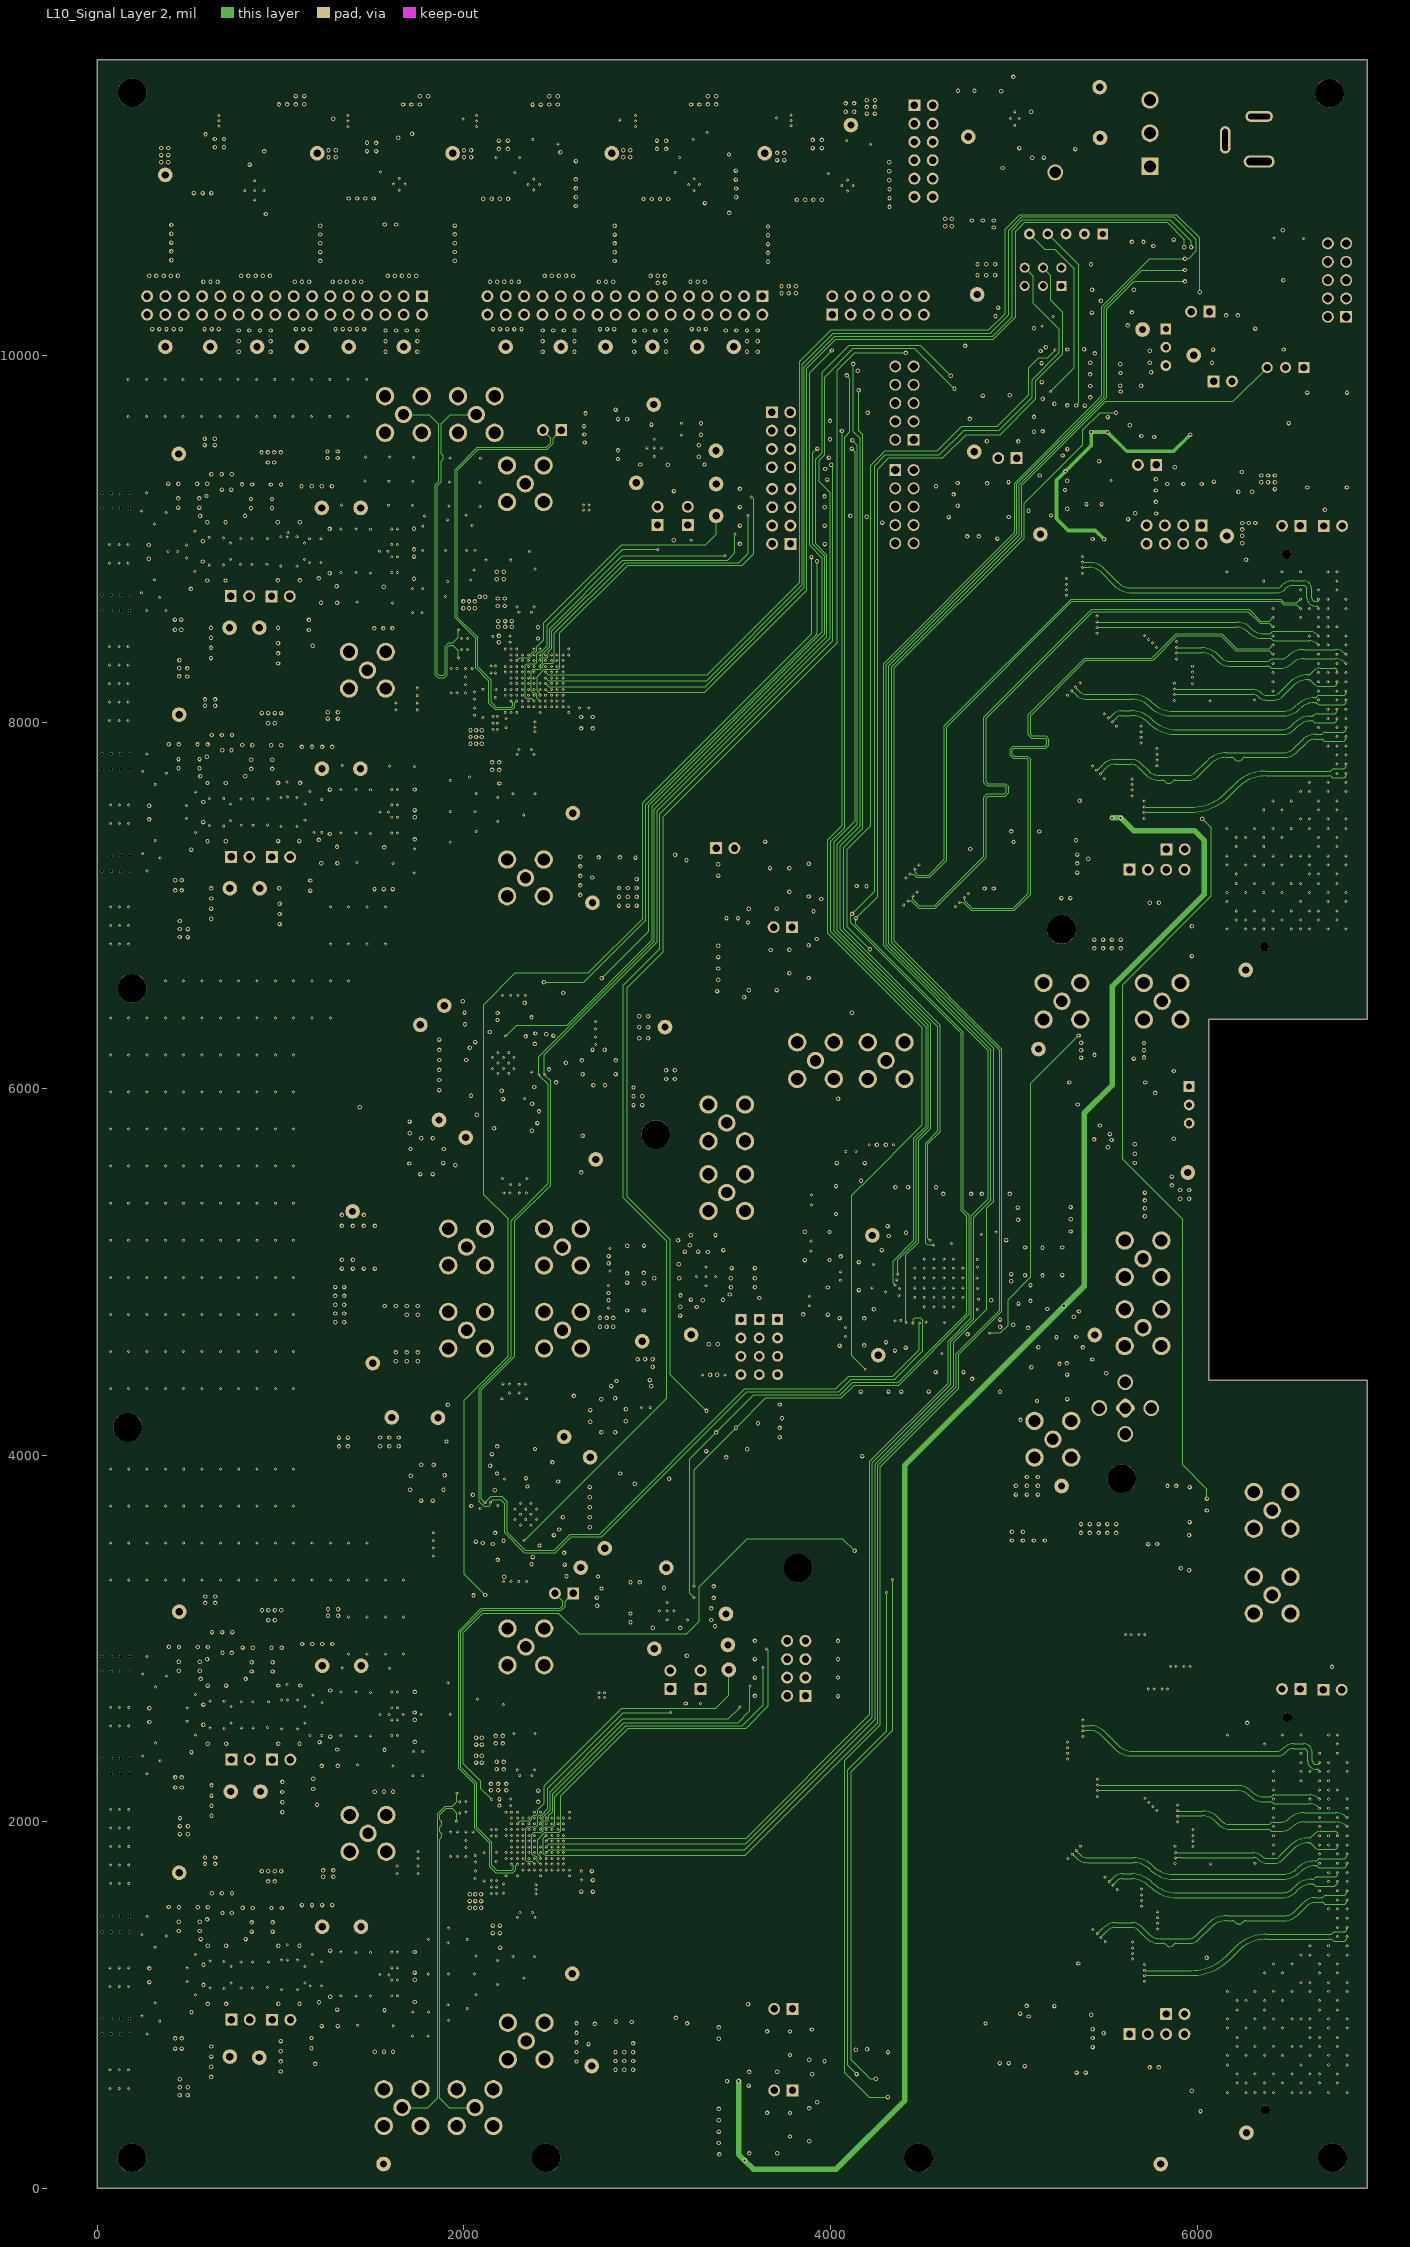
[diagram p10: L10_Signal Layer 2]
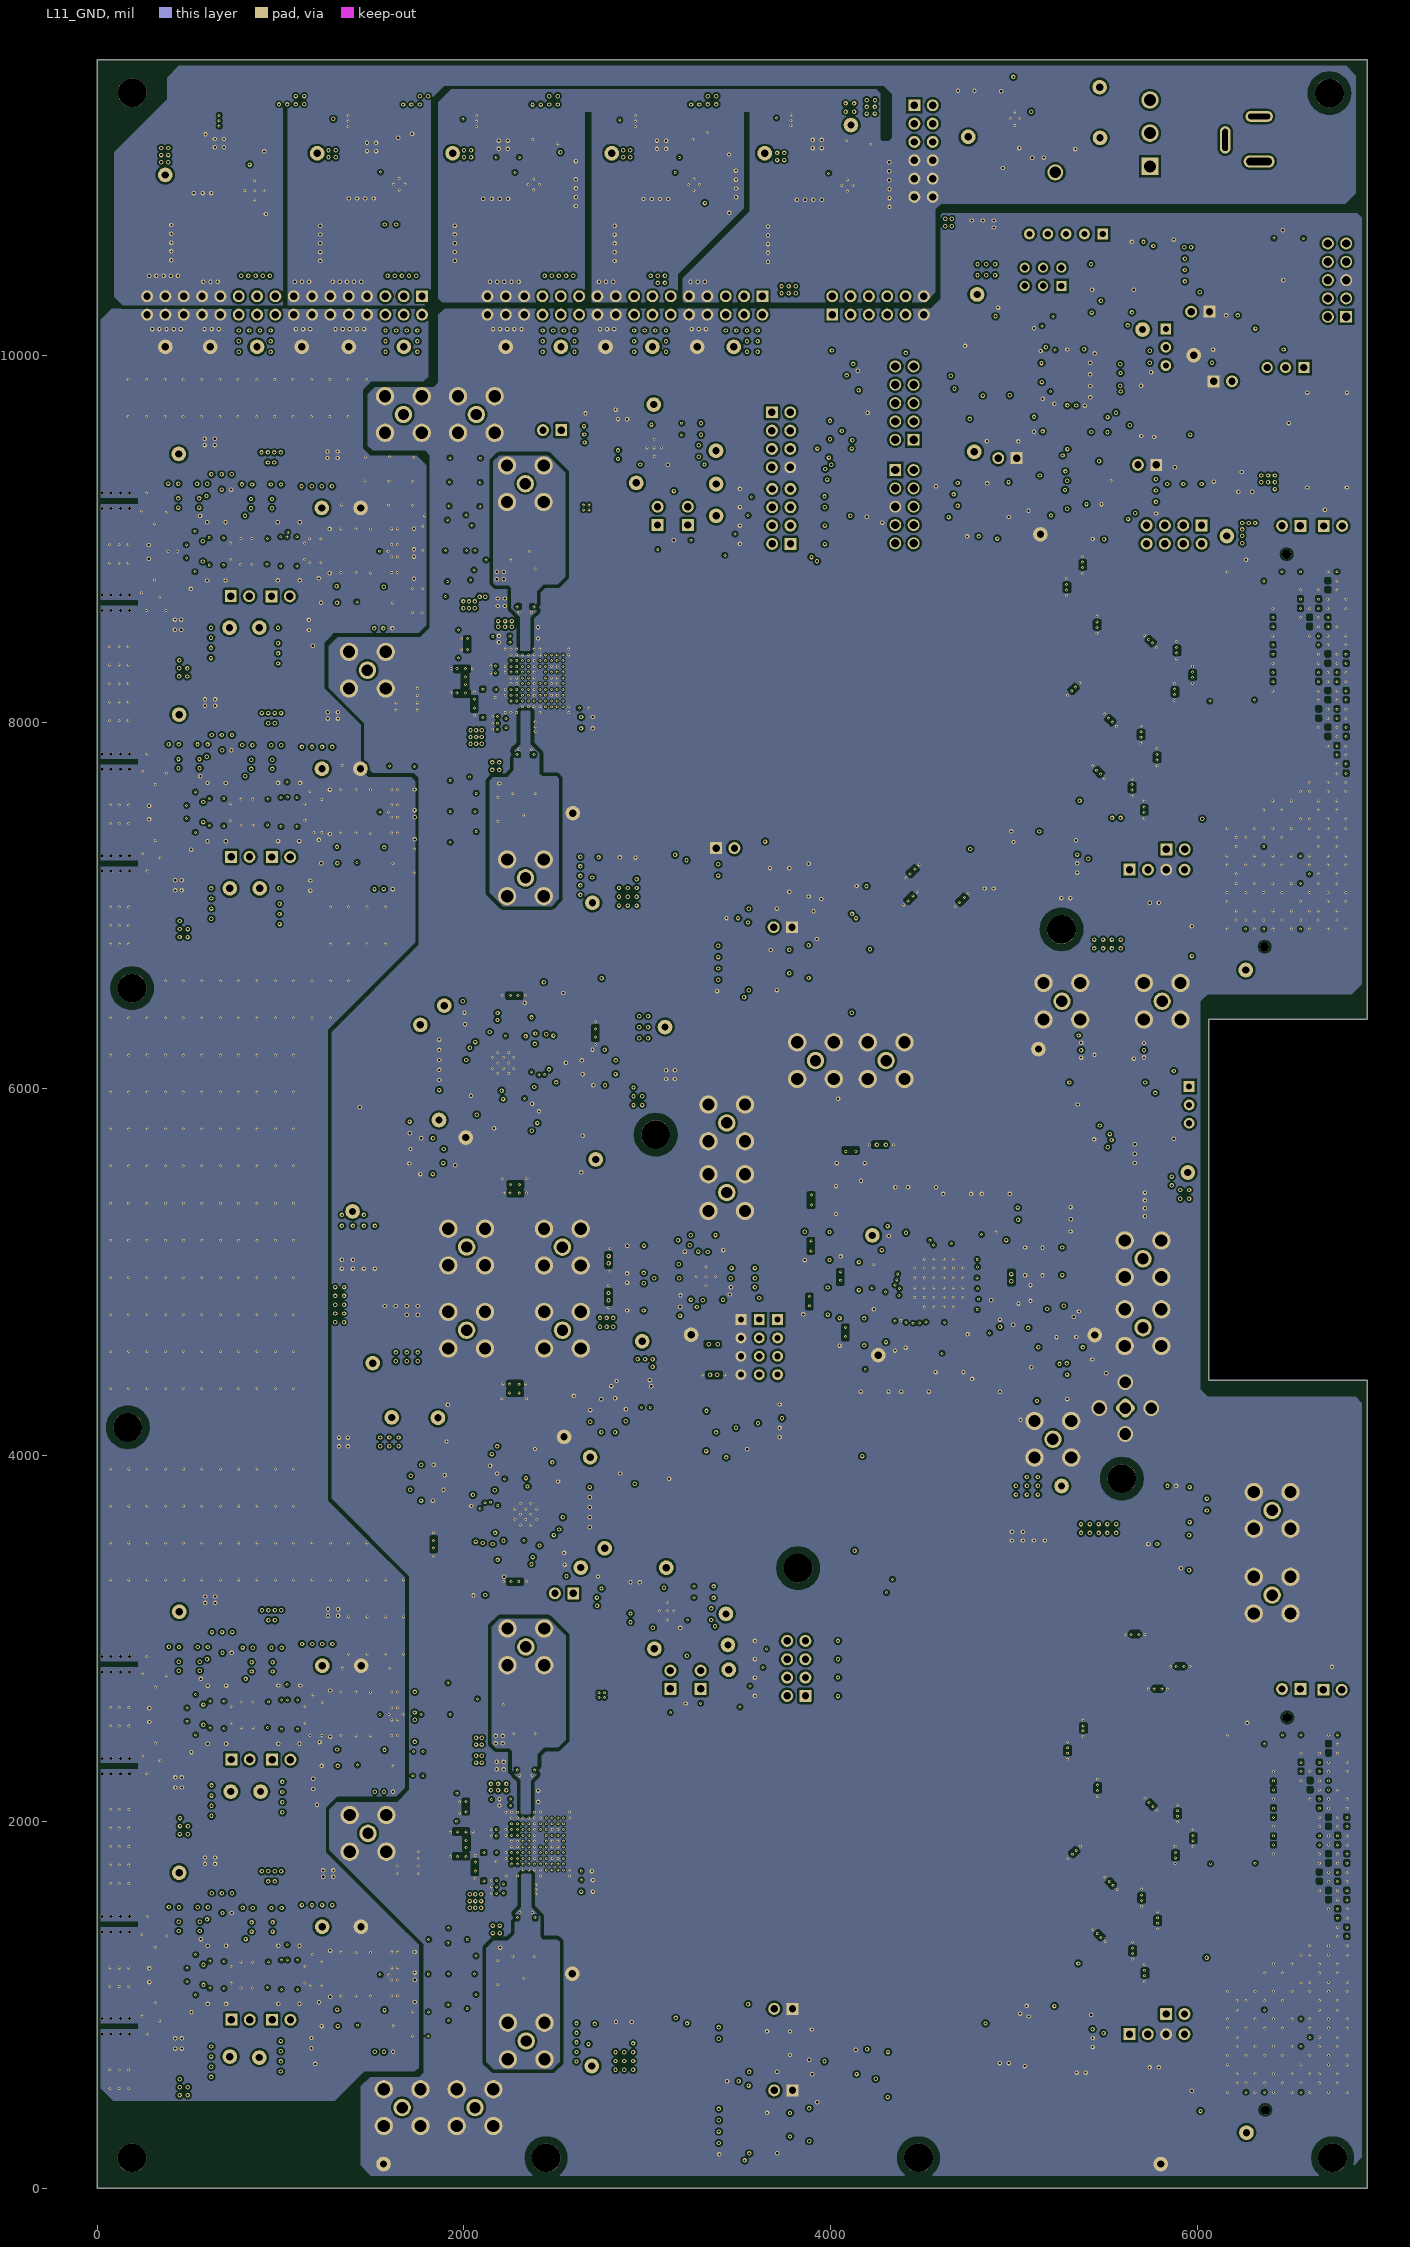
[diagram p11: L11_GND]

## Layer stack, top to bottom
Top Solder: solder mask 0.4, Solder Resist, Dk 3.5
L1_Top Layer: signal copper 1.4
Dielectric1: core 5.6, R-5670k, Dk 4.2
L2_GND: signal copper 0.6
Dielectric 2: prepreg 5, R-5775K, Dk 4.2
L3_GND: signal copper 0.6
Dielectric 3: core 7.5, R-5670k, Dk 4.2
L4_Signal Layer 1: signal copper 0.6
Dielectric 4: prepreg 4, R-5775K, Dk 4.2
L5_GND: signal copper 0.6
Dielectric 5: core 4.3, R-5670k, Dk 4.2
L6_PWR: signal copper 0.6
Dielectric 6: prepreg 3, R-5775K, Dk 4.2
L7_GND/PWR: signal copper 0.6
Dielectric 7: core 4.3, R-5670k, Dk 4.2
L8_PWR: signal copper 0.6
Dielectric 8: prepreg 4, R-5775K, Dk 4.2
L9_GND/PWR: signal copper 0.6
Dielectric 9: core 7.5, R-5670k, Dk 4.2
L10_Signal Layer 2: signal copper 0.6
Dielectric 10: prepreg 5, R-5775K, Dk 4.2
L11_GND: signal copper 0.6
Dielectric 11: core 5.6, R-5670k, Dk 4.2
L12_Bottom Layer: signal copper 1.4
Bottom Solder: solder mask 0.4, Solder Resist, Dk 3.5

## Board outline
0,0 0,11614.17 6929.13,11614.17 6929.13,6377.95 6062.99,6377.95 6062.99,4409.45 6929.13,4409.45 6929.13,0

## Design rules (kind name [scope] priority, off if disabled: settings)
AcuteAngle [All] p1: minimum=4.50000000000000E+0001 checktracksonly=FALSE
AssemblyTestPointUsage [All] p1: valid=2
Clearance Clearance_diff [InAnyDifferentialPair vs InAnyDifferentialPair] p1: gap=6 except(5: Arc-Track Track-Track)
Clearance "Clearance_MH to Copper" [InPadClass('MH') vs InPolygon] p2: gap=40
Clearance "Clearance_top _poly" [InPoly vs OnLayer('L1_Top Layer')] p3: gap=20
Clearance Clearance_U_PAD [InPadClass('U1')] p4: gap=5.5
Clearance Clearance_adc2 [WithinRoom('TIDA-01022-E2_ADC12DJxx00_2')] p5: gap=5
Clearance Clearance_adc1 [WithinRoom('TIDA-01022-E2_ADC12DJxx00_1')] p6: gap=5
Clearance Clearance_Poly [InPolygon vs InPolygon] p7: gap=20
Clearance "Clearance_Poly to All" [IsVia or IsTrack or IsSMTPin or IsThruPin vs InPolygon] p8: gap=12 except(10: Via-Poly)
Clearance [All] p9: gap=6
ComponentClearance ComponentClearance_Shunt [InComponentClass('Header') vs InComponentClass('Shunt')] p1: gap=0 collisioncheckmode=3 verticalgap=0 showdistances=FALSE
ComponentClearance ComponentClearance_Logo [InComponentClass('Logo')] p2: gap=50 collisioncheckmode=3 verticalgap=10 showdistances=FALSE
ComponentClearance ComponentClearance_ScrewToNut [(HasFootprint('NY PMS 440 0025 PH')) vs (HasFootprint('Keystone_1902C'))] p3: gap=5 collisioncheckmode=3 verticalgap=10 showdistances=FALSE
ComponentClearance ComponentClearance_MountingHoles [InComponentClass('Mounting Holes')] p4: gap=250 collisioncheckmode=3 verticalgap=100000 showdistances=FALSE
ComponentClearance ComponentClearance_SmallPassives [HasFootprint('0201*') or HasFootprint('0402*') or HasFootprint('0508') or HasFootprint('0603*') or HasFootprint('0612') or HasFootprint('0805*') or HasFootprint('0815*') or HasFootprint('0830*') or HasFootprint('1206*') or HasFootprint('1210*') or HasFootprint('1808*') or HasFootprint('1812*') or HasFootprint('1825*') or HasFootprint('2010*') or HasFootprint('2220*') or HasFootprint('2225*') or HasFootprint('2512*') or HasFootprint('2728*') or HasFootprint('3518*') vs HasFootprint('0201*') or HasFootprint('0402*') or HasFootprint('0508') or HasFootprint('0603*') or HasFootprint('0612') or HasFootprint('0805*') or HasFootprint('0815*') or HasFootprint('0830*') or HasFootprint('1206*') or HasFootprint('1210*') or HasFootprint('1808*') or HasFootprint('1812*') or HasFootprint('1825*') or HasFootprint('2010*') or HasFootprint('2220*') or HasFootprint('2225*') or HasFootprint('2512*') or HasFootprint('2728*') or HasFootprint('3518*')] p5: gap=20 collisioncheckmode=3 verticalgap=10 showdistances=FALSE
ComponentClearance ComponentClearance_THtoSMT [IsThruComponent vs IsSMTComponent] p6: gap=100 collisioncheckmode=3 verticalgap=30 showdistances=FALSE
ComponentClearance ComponentClearance_THtoTH [IsThruComponent vs IsThruComponent] p7: gap=118.11 collisioncheckmode=3 verticalgap=30 showdistances=FALSE
ComponentClearance [All] p8: gap=40 collisioncheckmode=3 verticalgap=10 showdistances=FALSE
DiffPairsRouting DiffPairsRouting_100ohm [InDifferentialPairClass('100OHM')] p1: maxlimit=20.1 minlimit=5 mostfreqgap=20.1 toplayer_maxgap=18 toplayer_prefgap=5 toplayer_minwidth=6 toplayer_maxwidth=10 toplayer_prefwidth=6 midlayer1_mingap=7.1 midlayer1_minwidth=4.9 midlayer1_maxwidth=5.5 midlayer1_prefwidth=5.5 midlayer2_mingap=6.5 midlayer2_minwidth=5.5 midlayer2_maxwidth=6.3 midlayer2_prefwidth=6.3 midlayer3_mingap=0 midlayer3_maxgap=0 midlayer3_prefgap=0 midlayer3_minwidth=0 midlayer3_maxwidth=0 midlayer3_prefwidth=0 midlayer4_mingap=0 midlayer4_maxgap=0 midlayer4_prefgap=0 midlayer4_minwidth=0 midlayer4_maxwidth=0 midlayer4_prefwidth=0 midlayer5_mingap=0 midlayer5_maxgap=0 midlayer5_prefgap=0 midlayer5_minwidth=0 midlayer5_maxwidth=0 midlayer5_prefwidth=0 midlayer6_mingap=0 midlayer6_maxgap=0 midlayer6_prefgap=0 midlayer6_minwidth=0 midlayer6_maxwidth=0 midlayer6_prefwidth=0 midlayer7_mingap=0 midlayer7_maxgap=0 midlayer7_prefgap=0 midlayer7_minwidth=0 midlayer7_maxwidth=0 midlayer7_prefwidth=0 midlayer8_mingap=0 midlayer8_maxgap=0 midlayer8_prefgap=0 midlayer8_minwidth=0 midlayer8_maxwidth=0 midlayer8_prefwidth=0 midlayer9_mingap=0 midlayer9_maxgap=0 midlayer9_prefgap=0 midlayer9_minwidth=0 midlayer9_maxwidth=0 midlayer9_prefwidth=0 midlayer10_mingap=0 midlayer10_maxgap=0 midlayer10_prefgap=0 midlayer10_minwidth=0 midlayer10_maxwidth=0 midlayer10_prefwidth=0 bottomlayer_maxgap=18 bottomlayer_prefgap=5 bottomlayer_minwidth=6 bottomlayer_maxwidth=10 bottomlayer_prefwidth=6 maxuncoupledlength=1000
DiffPairsRouting DiffPairsRouting_90OHM [InDifferentialPairClass('90ohm')] p2: maxlimit=6 minlimit=6 mostfreqgap=6 toplayer_minwidth=8.2 toplayer_maxwidth=8.2 toplayer_prefwidth=8.2 midlayer1_mingap=0 midlayer1_maxgap=0 midlayer1_prefgap=0 midlayer1_minwidth=0 midlayer1_maxwidth=0 midlayer1_prefwidth=0 midlayer2_mingap=0 midlayer2_maxgap=0 midlayer2_prefgap=0 midlayer2_minwidth=0 midlayer2_maxwidth=0 midlayer2_prefwidth=0 midlayer3_mingap=0 midlayer3_maxgap=0 midlayer3_prefgap=0 midlayer3_minwidth=0 midlayer3_maxwidth=0 midlayer3_prefwidth=0 midlayer4_mingap=0 midlayer4_maxgap=0 midlayer4_prefgap=0 midlayer4_minwidth=0 midlayer4_maxwidth=0 midlayer4_prefwidth=0 midlayer5_mingap=0 midlayer5_maxgap=0 midlayer5_prefgap=0 midlayer5_minwidth=0 midlayer5_maxwidth=0 midlayer5_prefwidth=0 midlayer6_mingap=0 midlayer6_maxgap=0 midlayer6_prefgap=0 midlayer6_minwidth=0 midlayer6_maxwidth=0 midlayer6_prefwidth=0 midlayer7_mingap=0 midlayer7_maxgap=0 midlayer7_prefgap=0 midlayer7_minwidth=0 midlayer7_maxwidth=0 midlayer7_prefwidth=0 midlayer8_mingap=0 midlayer8_maxgap=0 midlayer8_prefgap=0 midlayer8_minwidth=0 midlayer8_maxwidth=0 midlayer8_prefwidth=0 midlayer9_mingap=0 midlayer9_maxgap=0 midlayer9_prefgap=0 midlayer9_minwidth=0 midlayer9_maxwidth=0 midlayer9_prefwidth=0 midlayer10_mingap=0 midlayer10_maxgap=0 midlayer10_prefgap=0 midlayer10_minwidth=0 midlayer10_maxwidth=0 midlayer10_prefwidth=0 bottomlayer_mingap=0 bottomlayer_maxgap=0 bottomlayer_prefgap=0 bottomlayer_minwidth=0 bottomlayer_maxwidth=0 bottomlayer_prefwidth=0 maxuncoupledlength=500
FabricationTestPointUsage TestPointUsage [All] p1: valid=2 allowmultiple=FALSE
FabricationTestpoint Testpoint [All] p1: side=3 testpointundercomponent=TRUE minsize=40 maxsize=100 preferedsize=60 minholesize=0 maxholesize=40 preferedholesize=32 testpointgrid=1 allowsidetop=TRUE allowsidebottom=TRUE usegrid=TRUE gridtolerance=0.01
FanoutControl Fanout_LCC [IsLCC] p1: bgadir=Out bgaviamode=Centered fanoutstyle=Auto fanoutdirection=Alternating viagrid=1 // Fanout_LCC (Default Rule)
FanoutControl Fanout_BGA [IsBGA] p2: bgadir=Out bgaviamode=Centered fanoutstyle=Auto fanoutdirection=Alternating viagrid=1 // Fanout_BGA (Default Rule)
FanoutControl Fanout_Default [All] p4: bgadir=Out bgaviamode=Centered fanoutstyle=Auto fanoutdirection=Alternating viagrid=1 // Fanout_Default (Default Rule)
FanoutControl Fanout_Small [(CompPinCount < 5)] p5: bgadir=Out bgaviamode=Centered fanoutstyle=Auto fanoutdirection=OutThenIn viagrid=1 // Fanout_Small (Default Rule)
HoleSize [All] p1: absolutevalues=TRUE maxlimit=251 minlimit=7.87 maxpercent=80.000 minpercent=20.000
HoleToHoleClearance [All] p1: gap=6 allowstackedmicrovias=TRUE
MatchedLengths [InAnyDifferentialPair] p1: tolerance=5 checknetsindiffpair=TRUE checkdiffpairvsdiffpair=FALSE checkxsignals=FALSE checkothers=FALSE
MinimumAnnularRing MinimumAnnularRing_ThermalPadVias [IsVia and InAnyComponent] p1: minimumring=4
MinimumAnnularRing [All] p2: minimumring=4
MinimumSolderMaskSliver MinimumSolderMaskSliver_Logo [InComponentClass('Logo') vs InComponentClass('Logo')] p1: minsoldermaskwidth=0.7
MinimumSolderMaskSliver [All] p2: minsoldermaskwidth=3.94
PlaneConnect [All] p1: planeconnectstyle=Relief reliefexpansion=10 reliefentries=4 reliefconductorwidth=10 reliefairgap=10
PolygonConnect [All] p1: connectstyle=Direct reliefconductorwidth=20 reliefentries=4 polygonreliefangle="90 Angle" airgapwidth=15
RoomDefinition TIDA-01022-E2_ADC12DJxx00_2 [InComponentClass('TIDA-01022-E2_ADC12DJxx00_2')] p1: confinementstyle=ConfineIn formatcopy=TRUE lockcomponents=FALSE outline 2308.7,2113.17 2608.54,2113.17 2608.54,1693.46 2308.7,1693.46
RoomDefinition TIDA-01022-E2_ADC12DJxx00_1 [InComponentClass('TIDA-01022-E2_ADC12DJxx00_1')] p2: confinementstyle=ConfineIn formatcopy=TRUE lockcomponents=FALSE outline 2305.37,8445 2597.97,8445 2597.97,8025.29 2305.37,8025.29
RoutingVias ThermalPadVias [IsVia and InAnyComponent] p1: holewidth=7.87 width=19.68 viastyle="Through Hole" minholewidth=8 minwidth=16 maxholewidth=12.99 maxwidth=23.62
RoutingVias [All] p2: holewidth=12 width=24 viastyle="Through Hole" minholewidth=8 minwidth=16 maxholewidth=16 maxwidth=30
SMDToCorner [All] p1: distance=30000
SilkToSilkClearance [All] p1: silktosilkclearance=5
SilkToSolderMaskClearance SilkscreenOverComponentPads [IsPad] p1: minsilkscreentomaskgap=5 clearancetoexposedcopper=TRUE
SolderMaskExpansion [All] p1: expansion=2.5
Width Width_adc2 [WithinRoom('TIDA-01022-E2_ADC12DJxx00_2')] p1: maxlimit=10 minlimit=3.5 preferedwidth=5 midlayer3_minwidth=0 midlayer3_prefwidth=0 midlayer4_minwidth=0 midlayer4_prefwidth=0 midlayer5_minwidth=0 midlayer5_prefwidth=0 midlayer6_minwidth=0 midlayer6_prefwidth=0 midlayer7_minwidth=0 midlayer7_prefwidth=0 midlayer8_minwidth=0 midlayer8_prefwidth=0 midlayer9_minwidth=0 midlayer9_prefwidth=0 midlayer10_minwidth=0 midlayer10_prefwidth=0 minimp=50.000000 maximp=50.000000 favimp=50.000000
Width Width_adc1 [WithinRoom('TIDA-01022-E2_ADC12DJxx00_1')] p2: maxlimit=11 minlimit=3.5 preferedwidth=5 midlayer3_minwidth=0 midlayer3_prefwidth=0 midlayer4_minwidth=0 midlayer4_prefwidth=0 midlayer5_minwidth=0 midlayer5_prefwidth=0 midlayer6_minwidth=0 midlayer6_prefwidth=0 midlayer7_minwidth=0 midlayer7_prefwidth=0 midlayer8_minwidth=0 midlayer8_prefwidth=0 midlayer9_minwidth=0 midlayer9_prefwidth=0 midlayer10_minwidth=0 midlayer10_prefwidth=0 minimp=50.000000 maximp=50.000000 favimp=50.000000
Width [All] p3: maxlimit=100 minlimit=3.5 preferedwidth=11 midlayer1_prefwidth=5.5 midlayer2_prefwidth=6.5 midlayer3_minwidth=0 midlayer3_prefwidth=0 midlayer4_minwidth=0 midlayer4_prefwidth=0 midlayer5_minwidth=0 midlayer5_prefwidth=0 midlayer6_minwidth=0 midlayer6_prefwidth=0 midlayer7_minwidth=0 midlayer7_prefwidth=0 midlayer8_minwidth=0 midlayer8_prefwidth=0 midlayer9_minwidth=0 midlayer9_prefwidth=0 midlayer10_minwidth=0 midlayer10_prefwidth=0 bottomlayer_minwidth=5 minimp=50.000000 maximp=50.000000 favimp=50.000000 checkconnectedcopper=TRUE
15 further rules are at their usual default settings.

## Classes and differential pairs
differential pair class 90ohm: USB USB*
component class TIDA-01022-E2_Power4: C509 C637 C638 C639 C640 C641 C642 C643 C644 C645 C646 C647 C648 C649 C650 C651 C652 C653 C654 C655 C656 C657 C658 C659 C660 C663 C664 C665 C666 C667 C668 C669 C670 C671 C672 C673 C674 C675 L48 L49 L50 L51 L52 L53 L54 L55 L90 R525 R526 R527 R528 R529 R530 R531 R532 R625 R626 TP40 TP41 TP42 TP43 TP44 TP45 TP46 TP47 TP48 TP49 U48 U49 U50
component class TIDA-01022-E2_Power3: C371 C485 C486 C487 C488 C596 C597 C598 C599 C600 C601 C602 C603 C604 C605 C606 C607 C608 C609 C610 C611 C612 C613 C614 C615 C616 C619 C620 C621 C622 C623 C624 C625 C626 C627 C628 C629 C630 C631 C632 C633 C634 C635 C636 L41 L42 L43 L44 L45 L46 L47 L59 L73 L89 R513 R514 R515 R516 R517 R518 R519 R520 R521 R522 R523 R524 R621 R622 TP24 TP31 TP32 TP33 TP34 TP35 TP36 TP37 TP38 TP39 U45 U46 U47
component class TIDA-01022-E2_Power1: C134 C135 C136 C137 C138 C139 C140 C141 C142 C143 C144 C145 C146 C294 C295 C296 C297 C298 C299 C300 C301 C302 C303 C304 C305 C306 C355 C477 C478 C479 C480 C481 C482 C483 C484 C494 C495 C496 C497 C498 C501 C516 C517 C518 C519 C522 C523 C524 D19 D20 D21 J55 L35 L36 L57 L72 L87 L93 L94 L95 L96 Q3 R386 R387 R484 R485 R486 R487 R488 R489 R490 R491 R492 R493 R494 R495 R496 R497 R498 R499 R500 R613 R614 S17 TP5 TP11 TP17 TP18 TP19 TP20 TP21 TP22 TP23 TP51 TP52 TP53 TP64 TP65 TP66 TP67 TP68 TP69 TP70 TP71 TP72 TP73 TP74 TP75 TP76 TP77 U38 U39 U40 U41
component class TIDA-01022-E2_USB: C457 C458 C459 C460 C461 C462 C463 C464 C465 C466 C467 C468 C469 C470 C471 C472 C473 C474 C489 C736 C737 C738 C739 C740 C741 D17 D18 J62 J71 J72 J85 L32 L33 L34 R469 R470 R472 R539 R541 R542 R543 R544 R545 R546 R547 R548 R549 R550 R591 TP13 TP14 U34 U35 U54 U55 U56 U57 U58 Y2
component class "TIDA-01022-E2_Programming for ADC_LMK _LMX": C148 C441 C442 C443 C444 C445 C447 C448 C449 C450 C451 C452 C453 C454 C455 C456 J31 J32 J33 J34 J35 J36 J37 J38 J39 J40 J41 J42 J43 J44 R374 R375 R376 R377 R378 R379 R380 R381 R382 R383 R384 R385 R394 R396 R398 R400 R402 R404 R405 R406 R407 R408 R409 R410 R411 R416 R420 R421 R423 R424 R425 R426 R427 R428 R429 R430 R431 R432 R433 R434 R435 R436 R437 R438 R439 R440 R441 R445 R447 R449 R451 R452 R454 R455 R456 R458 R459 R461 R462 R464 R465 R467 R468 R593 R594 R595 R596 R597 R598 R599 R600 R601 R602 R603 U26 U27 U28 U29 U30 U31 U32 U33 U75
component class TIDA-01022-E2_LMX2594R_2: C352 C353 C354 C356 C357 C358 C359 C360 C361 C362 C363 C365 C366 C367 C368 C369 C370 C372 C373 C374 C375 C376 C377 C378 C379 C380 CE_TP2 D12 L19 L20 OSCinM2 OSCinP2 R205 R206 R208 R209 R210 R211 R212 R213 R214 R216 R217 R218 R219 R220 R221 R223 R224 R225 R226 R227 R230 R231 R232 R233 R234 R235 R236 R237 R238 R239 R240 R241 R242 R243 R244 RMPCLK2 RMPDIR2 U21 U22 Vtune_TP2
component class TIDA-01022-E2_LMX2594R_1: C322 C323 C324 C326 C327 C328 C329 C330 C331 C332 C333 C335 C336 C337 C338 C339 C340 C342 C343 C344 C345 C346 C347 C348 C349 C350 CE_TP1 D11 L17 L18 OSCinM1 OSCinP1 R164 R165 R167 R168 R169 R170 R171 R172 R173 R175 R176 R177 R178 R179 R180 R182 R183 R184 R185 R187 R189 R190 R191 R192 R193 R194 R195 R196 R197 R198 R199 R200 R201 R202 R203 RMPCLK1 RMPDIR1 U19 U20 Vtune_TP1
component class TIDA-01022-E2_LMK0482x: C351 C393 C394 C395 C396 C397 C398 C399 C400 C401 C402 C403 C404 C405 C406 C407 C408 C409 C410 C411 C412 C413 C414 C415 C416 C417 C418 C419 J26 J27 J28 J75 L21 L56 OSCinM3 OSCinP3 R163 R166 R271 R272 R273 R274 R275 R276 R277 R278 R279 R280 R281 R282 R283 R284 R285 R286 R287 R288 R289 R290 R291 R292 R293 R294 R295 R296 R297 R298 R299 R300 R301 R302 R303 R304 R305 R306 R307 R308 R309 R310 R311 R312 R313 R314 R315 R316 R317 R318 R319 R320 R321 R322 R323 R324 R325 R326 R327 R328 R329 R330 R331 R332 R333 R334 R335 R336 R337 R338 R339 R340 R341 R342 R343 R344 R345 R346 R347 R348 R349 R350 R351 R352 R353 R354 R355 R356 R357 R358 R359 R360 R361 R362 R363 R364 R365 R366 R367 R392 T3 U24 U25 Y1
component class "TIDA-01022-E2_LMK0482x _PWR": C307 C308 C420 C421 C422 C423 C424 C425 C426 C427 C428 C429 C430 C431 C432 C433 C434 C435 C436 C437 C438 C439 C440 C446 C508 C511 C512 D13 D14 D15 D16 J1 J2 J3 J4 J56 J57 J61 L22 L23 L24 L25 L26 L27 L28 L29 L30 L31 R228 R229 R368 R369 R370 R371 R372 R373 R393 R395 R397 R399 R401 R403 R586 R587 R588 R589 R590 R631 R632 R633 R634 R635 R636 R637 SYNC1 U63 U64 U74
component class TIDA-01022-E2_LMK00304_Buffer: C381 C382 C383 C384 C385 C386 C387 C388 C389 C390 C391 C392 J23 J24 J25 R245 R246 R247 R248 R249 R250 R251 R252 R253 R254 R255 R256 R257 R258 R259 R260 R261 R262 R263 R264 R265 R266 R267 R268 R269 R270 U23
component class TIDA-01022-E2_FMC+CONN2_2: J54 R480 R481 R482
component class TIDA-01022-E2_FMC+CONN2_1: 3P3V_RX2 C476 J50 J51 J52 J53 R478 R479 U37
component class TIDA-01022-E2_FMC+CONN1_2: J49 R475 R476 R477
component class TIDA-01022-E2_FMC+CONN1_1: 3P3V_RX1 C475 J45 J46 J47 J48 R473 R474 U36
component class "TIDA-01022-E2_ADC ANALOG INP CH4": C195 C196 C197 C198 C199 C200 C201 C202 C203 C204 C205 C206 C207 C208 C209 C210 C211 C212 C213 C214 C215 C216 C217 C218 C219 C220 C221 C222 C223 C224 C225 C226 C227 C228 C505 C506 C507 J74 J80 J81 J83 J84 L13 L14 L15 L16 L81 L82 LF7 LF8 R106 R107 R108 R109 R110 R111 R112 R113 R114 R115 R116 R117 R118 R119 R120 R121 R122 R123 R124 R125 R126 R127 R128 R129 R215 R222 R577 R578 R579 R580 R581 R582 R583 R584 R585 R609 R610 R644 R645 R670 R671 R672 R673 R674 R675 R676 R677 U13 U14 U15 U62 U71 U72
component class "TIDA-01022-E2_ADC ANALOG INP CH3": C161 C162 C163 C164 C165 C166 C167 C168 C169 C170 C171 C172 C173 C174 C175 C176 C177 C178 C179 C180 C181 C182 C183 C184 C185 C186 C187 C188 C189 C190 C191 C192 C193 C194 C502 C503 C504 J29 J76 J77 J79 J82 L9 L10 L11 L12 L79 L80 LF5 LF6 R82 R83 R84 R85 R86 R87 R88 R89 R90 R91 R92 R93 R94 R95 R96 R97 R98 R99 R100 R101 R102 R103 R104 R105 R204 R207 R568 R569 R570 R571 R572 R573 R574 R575 R576 R607 R608 R642 R643 R662 R663 R664 R665 R666 R667 R668 R669 U10 U11 U12 U61 U69 U70
component class "TIDA-01022-E2_ADC ANALOG INP CH2": C35 C36 C37 C38 C39 C40 C41 C42 C43 C44 C45 C46 C47 C48 C49 C50 C51 C52 C53 C54 C55 C56 C57 C58 C59 C60 C61 C62 C63 C64 C65 C66 C67 C68 C493 C499 C500 J15 J30 J68 J73 J78 L5 L6 L7 L8 L77 L78 LF3 LF4 R25 R26 R27 R28 R29 R30 R31 R32 R33 R34 R35 R36 R37 R38 R39 R40 R41 R42 R43 R44 R45 R46 R47 R48 R186 R188 R559 R560 R561 R562 R563 R564 R565 R566 R567 R605 R606 R640 R641 R654 R655 R656 R657 R658 R659 R660 R661 U4 U5 U6 U60 U67 U68
component class "TIDA-01022-E2_ADC ANALOG INP CH1": C1 C2 C3 C4 C5 C6 C7 C8 C9 C10 C11 C12 C13 C14 C15 C16 C17 C18 C19 C20 C21 C22 C23 C24 C25 C26 C27 C28 C29 C30 C31 C32 C33 C34 C490 C491 C492 J12 J13 J14 J64 J67 L1 L2 L3 L4 L75 L76 LF1 LF2 R1 R2 R3 R4 R5 R6 R7 R8 R9 R10 R11 R12 R13 R14 R15 R16 R17 R18 R19 R20 R21 R22 R23 R24 R174 R181 R483 R551 R552 R553 R554 R555 R556 R557 R558 R592 R604 R638 R639 R646 R647 R648 R649 R650 R651 R652 R653 U1 U2 U3 U59 U65 U66
component class TIDA-01022-E2_ADC12DJxx00_2: BG2 C229 C230 C231 C232 C233 C234 C235 C236 C237 C238 C239 C240 C241 C242 C243 C244 C245 C246 C247 C248 C249 C250 C251 C252 C253 C254 C255 C256 C257 C258 C259 C260 C261 C262 C263 C264 C265 C266 C267 C268 C269 C270 C271 C272 C273 C274 C275 C276 C277 C278 C334 C341 CALSAT2 D6 D7 D8 D9 D10 J16 J17 J18 J19 J20 J21 J22 Q2 R130 R131 R132 R133 R134 R135 R136 R137 R138 R139 R140 R141 R142 R143 R144 R145 R146 R147 R148 R149 R150 R151 R152 R153 R154 R155 R156 R157 R158 R159 R160 R161 R162 T2 TP7 TP8 TP9 U16 U17 U18
component class TIDA-01022-E2_ADC12DJxx00_1: BG1 C69 C70 C71 C72 C73 C74 C75 C76 C77 C78 C79 C80 C81 C82 C83 C84 C85 C86 C87 C88 C89 C90 C91 C92 C93 C94 C95 C96 C97 C98 C99 C100 C101 C102 C103 C104 C105 C106 C107 C108 C109 C110 C111 C112 C113 C114 C115 C116 C117 C118 C321 C325 CALSAT1 D1 D2 D3 D4 D5 J5 J6 J7 J8 J9 J10 J11 Q1 R49 R50 R51 R52 R53 R54 R55 R56 R57 R58 R59 R60 R61 R62 R63 R64 R65 R66 R67 R68 R69 R70 R71 R72 R73 R74 R75 R76 R77 R78 R79 R80 R81 T1 TP1 TP2 TP3 U7 U8 U9
component class TIDA-01022-E2_Power2: C119 C120 C121 C122 C123 C124 C125 C126 C127 C128 C129 C130 C131 C132 C133 C149 C150 C151 C152 C153 C154 C155 C156 C157 C158 C159 C160 C279 C280 C281 C282 C283 C284 C285 C286 C287 C288 C289 C290 C291 C292 C293 C309 C310 C311 C312 C313 C314 C315 C316 C317 C318 C319 C320 C364 C537 C538 C539 C540 C541 C544 C587 C588 C589 C590 C593 C594 C595 L37 L38 L39 L40 L58 L88 R388 R389 R501 R502 R503 R504 R505 R506 R507 R508 R509 R510 R511 R512 R617 R618 TP4 TP6 TP10 TP12 TP25 TP26 U42 U43 U44
pad class MH: S1-1 S2-1 S3-1 S4-1 S5-1 S6-1 S7-1 S8-1 S9-1 S10-1 S11-1 S12-1
pad class U1: U39-0 U39-1 U39-2 U39-3 U39-4 U39-5 U39-6 U39-7 U39-8 U39-9 U42-0 U42-1 U42-2 U42-3 U42-4 U42-5 U42-6 U42-7 U42-8 U42-9 U45-0 U45-1 U45-2 U45-3 U45-4 U45-5 U45-6 U45-7 U45-8 U45-9 U48-0 U48-1 U48-2 U48-3 U48-4 U48-5 U48-6 U48-7 U48-8 U48-9 U51-0 U51-1 U51-2 U51-3 U51-4 U51-5 U51-6 U51-7 U51-8 U51-9
component class TIDA-01022-E2_Hardware: FID1 FID2 FID3 FID4 FID5 FID6 LBL1 Logo1 Logo2 Logo3 Logo4 Logo5 S1 s1 S2 S3 S4 S5 S6 S7 S8 S9 S10 S11 S12 ZZ1 ZZ2 ZZ3 ZZ4
component class FiducialMark: FID1 FID2 FID3 FID4 FID5 FID6
component class AssemblyNote: ZZ1 ZZ2 ZZ3 ZZ4
component class Label: LBL1
component class Header: J5 J6 J7 J11 J16 J17 J18 J22 J23 J24 J25 J31 J32 J34 J35 J36 J37 J38 J39 J40 J41 J42 J43 J44 J45 J47 J48 J49 J50 J52 J53 J54 J58 J59 J60 J62 J63 J64 J67 J68 J71 J75 J78 J79 J82 J83 J84 J85
differential pair class 100OHM: 1 ADC1_CLK ADC1_CLK* ADC1_DA0 ADC1_DA0* ADC1_DA1 ADC1_DA1* ADC1_DA2 ADC1_DA2* ADC1_DA3 ADC1_DA3* ADC1_DA4 ADC1_DA4* ADC1_DA5 ADC1_DA5* ADC1_DA6 ADC1_DA6* ADC1_DA7 ADC1_DA7* ADC1_DB0 ADC1_DB0* ADC1_DB1 ADC1_DB1* ADC1_DB2 ADC1_DB2* ADC1_DB3 ADC1_DB3* ADC1_DB4 ADC1_DB4* ADC1_DB5 ADC1_DB5* ADC1_DB6 ADC1_DB6* ADC1_DB7 ADC1_DB7* ADC1_SYNC ADC1_SYS1 ADC1_TMSTP ADC1_TMSTP* ADC2_CLK ADC2_CLK* ADC2_DA0 ADC2_DA0* ADC2_DA1 ADC2_DA1* ADC2_DA2 ADC2_DA2* ADC2_DA3 ADC2_DA3* ADC2_DA4 ADC2_DA4* ADC2_DA5 ADC2_DA5* ADC2_DA6 ADC2_DA6* ADC2_DA7 ADC2_DA7* ADC2_DB0 ADC2_DB0* ADC2_DB1 ADC2_DB1* ADC2_DB2 ADC2_DB2* ADC2_DB3 ADC2_DB3* ADC2_DB4 ADC2_DB4* ADC2_DB5 ADC2_DB5* ADC2_DB6 ADC2_DB6* ADC2_DB7 ADC2_DB7* ADC2_SYNC ADC2_SYS2 ADC2_TMSTP ADC2_TMSTP* AF_OUT1 AF_OUT1* AF_OUT1** AF_OUT1*** AF_OUT2 AF_OUT2* AF_OUT2** AF_OUT2*** AF_OUT3 AF_OUT3* AF_OUT3** AF_OUT3*** AF_OUT4 AF_OUT4* AF_OUT4** AF_OUT4*** B_VIN1 B_VIN2 B_VIN3 B_VIN4 CLKIN0 CLKIN0* CLKIN1 CLKIN1* CLKIN1** CLKINP** CR_OSC DCLKOUT0 DCLKOUT2 DCLKOUT12 DCLKOUT12* F_CORECLK1 F_CORECLK1* F_CORECLK2 F_CORECLK2* F_OUT1 F_OUT2 F_OUT3 F_OUT4 F_REFCLK1 F_REFCLK1* F_REFCLK2 F_REFCLK2* F_SYSREF1 F_SYSREF1* F_SYSREF2 F_SYSREF2* IN1 IN1* IN2 IN2* IN3 IN3* IN4 IN4* LMK_ADC1_SYSREF LMK_ADC2_DCLK LMK_ADC2_SYSREF LMX1_CLK LMX1_REF LMX1_REF* LMX2_CLK LMX2_REF LMX2_REF* LMX_ADC1_DCLK LMX_ADC1_DCLK* LMX_ADC1_SYSREF LMX_ADC2_DCLK* LMX_ADC2_SYSREF LMX_OSCIN1 LMX_OSCIN2 OSCIN OSCIN* OSCOUT OSCOUT* OSCOUT** OSCOUT*** SDCLKOUT1 SDCLKOUT1* SDCLKOUT3 SDCLKOUT3* SDCLKOUT5 SDCLKOUT5* SDCLKOUT5** SDCLKOUT11 SDCLKOUT11* SDCLKOUT11** SDCLKOUT13 SDCLKOUT13* SDCLKOUT13** TDIODE1 TDIODE1* TDIODE2 TDIODE2* VIN1 VIN2 VIN3 VIN4
component class TIDA-01022-E2_Power5: C147 C510 C688 C689 C690 C691 C692 C693 C694 C695 C696 C697 C698 C699 C700 C701 C702 C703 C704 C705 C706 C707 C708 C709 C710 C711 C712 C713 C714 C715 C716 C717 C718 C719 C720 C721 C722 C723 J58 J59 J60 J63 L60 L61 L62 L63 L64 L65 L66 L67 L68 L69 L70 L71 L74 L83 L84 L85 L86 L91 L92 R390 R391 R533 R534 R535 R536 R537 R629 R630 TP15 TP16 TP27 TP28 TP29 TP30 TP50 TP54 TP55 TP56 TP57 TP58 TP59 TP60 TP61 TP62 TP63 U51 U52 U53 U73
component class Screw: H1 H2 H3 H4 H5 H6 H7 H8 H9 H10 H11 H12 H13 H14 H15 H16
differential pair SDCLKOUT13**: +NetR391_2 -NetR390_2
differential pair B_VIN4: +NetR578_1 -NetR579_1
differential pair B_VIN3: +NetR569_1 -NetR570_1
differential pair B_VIN2: +NetR560_1 -NetR561_1
differential pair B_VIN1: +NetR551_1 -NetR552_1
differential pair IN3*: +NetC502_1 -NetC503_2
differential pair IN4*: +NetC505_1 -NetC506_2
differential pair AF_OUT4: +NetR114_1 -NetR118_1
differential pair AF_OUT4*: +NetR115_1 -NetR119_1
differential pair AF_OUT4**: +NetR116_2 -NetR120_2
differential pair AF_OUT3: +NetR90_1 -NetR94_1
differential pair AF_OUT3*: +NetR91_1 -NetR95_1
differential pair AF_OUT3**: +NetR92_2 -NetR96_2
differential pair AF_OUT2**: +NetR35_2 -NetR39_2
differential pair AF_OUT2*: +NetR34_1 -NetR38_1
differential pair AF_OUT2: +NetR33_1 -NetR37_1
differential pair IN2*: +NetC493_1 -NetC499_2
differential pair AF_OUT1**: +NetR11_2 -NetR15_2
differential pair AF_OUT1*: +NetR10_1 -NetR14_1
differential pair AF_OUT1: +NetR9_1 -NetR13_1
differential pair CR_OSC: +OSCO -OSCI
differential pair USB: +DP -DM
differential pair USB*: +USB_DP -USB_DM
differential pair LMX2_CLK: +LMX2_CLKP -LMX2_CLKM
differential pair LMX1_CLK: +LMX1_CLKP -LMX1_CLKM
differential pair LMX_ADC2_SYSREF: +LMX_ADC2_SYSREF_P -LMX_ADC2_SYSREF_M
differential pair LMX_ADC1_SYSREF: +LMX_ADC1_SYSREF_P -LMX_ADC1_SYSREF_M
differential pair SDCLKOUT11**: +SDCLKOUT11+* -SDCLKOUT11-*
differential pair OSCIN*: +OSCIN+ -OSCIN-
differential pair CLKIN1**: +CLKINP -CLKINN
differential pair CLKIN1*: +CLKINN* -CLKINP*
differential pair CLKIN0*: +CLKINP0 -CLKINN0
differential pair SDCLKOUT13*: +SDCLKOUT13+ -SDCLKOUT13-
differential pair DCLKOUT12*: +DCLKOUT12+ -DCLKOUT12-
differential pair SDCLKOUT11*: +SDCLKOUT11+ -SDCLKOUT11-
differential pair F_REFCLK1*: +F_REFCLK1+ -F_REFCLK1-
differential pair F_SYSREF2*: +F_SYSREF2+ -F_SYSREF2-
differential pair F_SYSREF1*: +F_SYSREF1+ -F_SYSREF1-
differential pair F_CORECLK1*: +F_CORECLK1+ -F_CORECLK1-
differential pair F_CORECLK2*: +F_CORECLK2+ -F_CORECLK2-
differential pair SDCLKOUT5**: +SDCLKOUT5+* -SDCLKOUT5-*
differential pair SDCLKOUT5*: +SDCLKOUT5+ -SDCLKOUT5-
differential pair F_REFCLK2*: +F_REFCLK2+ -F_REFCLK2-
differential pair SDCLKOUT3*: +SDCLKOUT3+* -SDCLKOUT3-*
differential pair SDCLKOUT3: +SDCLKOUT3+ -SDCLKOUT3-
differential pair DCLKOUT2: +DCLKOUT2+ -DCLKOUT2-
differential pair SDCLKOUT1*: +NetR276_1 -NetR279_1
differential pair SDCLKOUT1: +SDCLKOUT1+ -SDCLKOUT1-
differential pair DCLKOUT0: +DCLKOUT0+ -DCLKOUT0-
differential pair OSCOUT***: +NetR252_2 -NetR256_2
differential pair OSCOUT**: +NetR260_2 -NetR265_2
differential pair LMX2_REF*: +NetR262_1 -NetR264_1
differential pair LMX1_REF*: +NetR254_1 -NetR255_1
differential pair LMX2_REF: +LMX2_REFP -LMX2_REFN
differential pair LMX1_REF: +LMX1_REFP -LMX1_REFN
differential pair OSCOUT*: +NetC391_2 -NetC392_2
differential pair LMX_OSCIN2: +LMX_OSCIN2+ -LMX_OSCIN2-
differential pair LMX_OSCIN1: +LMX_OSCIN1+ -LMX_OSCIN1-
differential pair VIN4: +VIN4_P -VIN4_N
differential pair VIN3: +VIN3_P -VIN3_N
differential pair VIN2: +VIN2_P -VIN2_N
differential pair VIN1: +VIN1_P -VIN1_N
differential pair IN4: +IN4_P -IN4_N
differential pair IN3: +IN3_P -IN3_N
differential pair IN2: +IN2_P -IN2_N
differential pair IN1: +IN1_P -IN1_N
differential pair CLKIN0: +CLKIN0_P -CLKIN0_N
differential pair CLKIN1: +CLKIN1_P -CLKIN1_N
differential pair DCLKOUT12: +DCLKOUT12_P -DCLKOUT12_N
differential pair F_CORECLK1: +F_CORECLK1_P -F_CORECLK1_N
differential pair F_CORECLK2: +F_CORECLK2_P -F_CORECLK2_N
differential pair F_REFCLK1: +F_REFCLK1_P -F_REFCLK1_N
differential pair F_REFCLK2: +F_REFCLK2_P -F_REFCLK2_N
differential pair F_SYSREF1: +F_SYSREF1_P -F_SYSREF1_N
differential pair F_SYSREF2: +F_SYSREF2_P -F_SYSREF2_N
differential pair OSCIN: +OSCIN_P -OSCIN_N
differential pair OSCOUT: +OSCOUT_P -OSCOUT_N
differential pair SDCLKOUT5: +SDCLKOUT5_P -SDCLKOUT5_N
differential pair SDCLKOUT11: +SDCLKOUT11_P -SDCLKOUT11_N
differential pair SDCLKOUT13: +SDCLKOUT13_P -SDCLKOUT13_N
differential pair LMK_ADC1_SYSREF: +LMK_ADC1_SYSREF_P -LMK_ADC1_SYSREF_M
differential pair LMK_ADC2_SYSREF: +LMK_ADC2_SYSREF_P -LMK_ADC2_SYSREF_M
differential pair TDIODE1*: +TDIODE1N -TDIODE1P
differential pair TDIODE2*: +TDIODE2P -TDIODE2N
differential pair ADC1_CLK: +CLK_1+ -CLK_1-
differential pair ADC2_CLK: +CLK_2+ -CLK_2-
differential pair ADC1_CLK*: +CLK1+* -CLK1-*
differential pair ADC2_CLK*: +CLK2+* -CLK2-*
differential pair ADC1_TMSTP: +TMSTP1+ -TMSTP1-
differential pair ADC2_TMSTP: +TMSTP2+ -TMSTP2-
differential pair ADC1_TMSTP*: +TMSP1+ -TMSP1-
differential pair ADC2_TMSTP*: +TMSP2+ -TMSP2-
differential pair ADC1_SYS1: +SYS1+ -SYS1-
differential pair ADC2_SYS2: +SYS2+ -SYS2-
differential pair ADC1_DA0: +ADC1_DA0+ -ADC1_DA0-
differential pair ADC1_DA0*: +ADC1_DA0_P -ADC1_DA0_M
differential pair ADC1_DA1*: +ADC1_DA1_P -ADC1_DA1_M
differential pair ADC1_DA1: +ADC1_DA1+ -ADC1_DA1-
differential pair ADC1_DA2: +ADC1_DA2+ -ADC1_DA2-
differential pair ADC1_DA2*: +ADC1_DA2_P -ADC1_DA2_M
differential pair ADC1_DA3: +ADC1_DA3+ -ADC1_DA3-
differential pair ADC1_DA3*: +ADC1_DA3_P -ADC1_DA3_M
differential pair ADC1_DA4: +ADC1_DA4+ -ADC1_DA4-
differential pair ADC1_DA4*: +ADC1_DA4_P -ADC1_DA4_M
differential pair ADC1_DA5: +ADC1_DA5+ -ADC1_DA5-
differential pair ADC1_DA5*: +ADC1_DA5_P -ADC1_DA5_M
differential pair ADC1_DA6: +ADC1_DA6+ -ADC1_DA6-
differential pair ADC1_DA6*: +ADC1_DA6_P -ADC1_DA6_M
differential pair ADC1_DA7: +ADC1_DA7+ -ADC1_DA7-
differential pair ADC1_DA7*: +ADC1_DA7_P -ADC1_DA7_M
differential pair ADC1_DB1: +ADC1_DB1+ -ADC1_DB1-
differential pair ADC1_DB1*: +ADC1_DB1_P -ADC1_DB1_M
differential pair ADC1_DB2: +ADC1_DB2+ -ADC1_DB2-
differential pair ADC1_DB2*: +ADC1_DB2_P -ADC1_DB2_M
differential pair ADC1_DB3: +ADC1_DB3+ -ADC1_DB3-
differential pair ADC1_DB3*: +ADC1_DB3_P -ADC1_DB3_M
differential pair ADC1_DB4: +ADC1_DB4+ -ADC1_DB4-
differential pair ADC1_DB4*: +ADC1_DB4_P -ADC1_DB4_M
differential pair ADC1_DB5: +ADC1_DB5+ -ADC1_DB5-
differential pair ADC1_DB5*: +ADC1_DB5_P -ADC1_DB5_M
differential pair ADC1_DB6: +ADC1_DB6+ -ADC1_DB6-
differential pair ADC1_DB6*: +ADC1_DB6_P -ADC1_DB6_M
differential pair ADC1_DB7: +ADC1_DB7+ -ADC1_DB7-
differential pair ADC1_DB7*: +ADC1_DB7_P -ADC1_DB7_M
differential pair ADC2_DA0: +ADC2_DA0+ -ADC2_DA0-
differential pair ADC2_DA0*: +ADC2_DA0_P -ADC2_DA0_M
differential pair ADC2_DA1: +ADC2_DA1+ -ADC2_DA1-
differential pair ADC2_DA1*: +ADC2_DA1_P -ADC2_DA1_M
differential pair ADC1_DB0: +ADC1_DB0+ -ADC1_DB0-
differential pair ADC1_DB0*: +ADC1_DB0_P -ADC1_DB0_M
differential pair ADC2_DA2: +ADC2_DA2+ -ADC2_DA2-
differential pair ADC2_DA2*: +ADC2_DA2_P -ADC2_DA2_M
differential pair ADC2_DA3: +ADC2_DA3+ -ADC2_DA3-
differential pair ADC2_DA3*: +ADC2_DA3_P -ADC2_DA3_M
differential pair ADC2_DA4: +ADC2_DA4+ -ADC2_DA4-
differential pair ADC2_DA4*: +ADC2_DA4_P -ADC2_DA4_M
differential pair ADC2_DA5: +ADC2_DA5+ -ADC2_DA5-
differential pair ADC2_DA5*: +ADC2_DA5_P -ADC2_DA5_M
differential pair ADC2_DA6: +ADC2_DA6+ -ADC2_DA6-
differential pair ADC2_DA6*: +ADC2_DA6_P -ADC2_DA6_M
differential pair ADC2_DA7: +ADC2_DA7+ -ADC2_DA7-
differential pair ADC2_DA7*: +ADC2_DA7_P -ADC2_DA7_M
differential pair ADC2_DB0: +ADC2_DB0+ -ADC2_DB0-
differential pair ADC2_DB0*: +ADC2_DB0_P -ADC2_DB0_M
differential pair ADC2_DB1: +ADC2_DB1+ -ADC2_DB1-
differential pair ADC2_DB1*: +ADC2_DB1_P -ADC2_DB1_M
differential pair ADC2_DB2: +ADC2_DB2+ -ADC2_DB2-
differential pair ADC2_DB2*: +ADC2_DB2_P -ADC2_DB2_M
differential pair ADC2_DB3: +ADC2_DB3+ -ADC2_DB3-
differential pair ADC2_DB3*: +ADC2_DB3_P -ADC2_DB3_M
differential pair ADC2_DB4: +ADC2_DB4+ -ADC2_DB4-
differential pair ADC2_DB4*: +ADC2_DB4_P -ADC2_DB4_M
differential pair ADC2_DB5: +ADC2_DB5+ -ADC2_DB5-
differential pair ADC2_DB5*: +ADC2_DB5_P -ADC2_DB5_M
differential pair ADC2_DB6: +ADC2_DB6+ -ADC2_DB6-
differential pair ADC2_DB6*: +ADC2_DB6_P -ADC2_DB6_M
differential pair ADC2_DB7: +ADC2_DB7+ -ADC2_DB7-
differential pair ADC2_DB7*: +ADC2_DB7_P -ADC2_DB7_M
differential pair ADC1_SYNC: +SYNC1_P -SYNC1_N
differential pair ADC2_SYNC: +SYNC2_P -SYNC2_N
differential pair LMX_ADC1_DCLK: +LMK_ADC1_DCLKP -LMK_ADC1_DCLKM
differential pair LMK_ADC2_DCLK: +LMK_ADC2_DCLKP -LMK_ADC2_DCLKM
differential pair LMX_ADC1_DCLK*: +NetR185_1 -NetR197_2
differential pair LMX_ADC2_DCLK*: +NetR238_2 -NetR226_1
differential pair IN1*: +NetC490_1 -NetC491_2
differential pair TDIODE1: +TDIODE1+ -TDIODE1-
differential pair TDIODE2: +TDIODE2+ -TDIODE2-
differential pair F_OUT1: +F_OUT1P -F_OUT1N
differential pair F_OUT2: +F_OUT2P -F_OUT2N
differential pair F_OUT3: +F_OUT3P -F_OUT3N
differential pair F_OUT4: +F_OUT4P -F_OUT4N
differential pair CLKINP**: +NetR399_2 -NetR395_2

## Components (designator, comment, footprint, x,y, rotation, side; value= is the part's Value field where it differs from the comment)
3P3V_RX1 "5000" Keystone5000 6265.36,6647.2 r90 top
3P3V_RX2 "5000" Keystone5000 6269,304 r90 top
BG1 "5002" Keystone5002 3375.44,9124.69 r0 top
BG2 "5002" Keystone5002 3444.77,2829.93 r0 top
C1 "GRM155R71E103KA01D" 0402#1 628.41,9125.99 r180 top
C2 "LLL185R71E103MA01L" 0306#1 598.91,9045.99 r270 top
C3 "LLL185R71E103MA01L" 0306#1 698.91,9045.99 r270 top
C4 "LLL185R71E103MA01L" 0306#1 984.09,9046.26 r270 top
C5 "LLL185R71E103MA01L" 0306#1 1099.09,9046.26 r270 top
C6 "LLL185R71H222MA01L" 0306#1 598.91,9045.99 r90 bottom
C7 "LLL185R71H222MA01L" 0306#1 698.91,9045.99 r90 bottom
C8 "LLL185R71H222MA01L" 0306#2 984.41,9045.99 r90 bottom
C9 "LLL185R71H222MA01L" 0306#3 1084.25,9056.1 r90 bottom
C10 "GRM1555C1H1R0CA01D" 0402#1 1266.72,8992.13 r90 top
C11 "GRM1555C1H2R4CA01D" 0402#1 1366.72,8992.13 r270 top
C12 "GRM155R71E103KA01D" 0402#1 1562.82,8931.82 r0 bottom
C13 "GRM155R71E103KA01D" 0402#1 363.91,9015.99 r315 top
C14 "GRM155R71E103KA01D" 0402#1 363.91,8840.99 r45 top
C15 "GRM1555C1H1R0CA01D" 0402#1 1266.72,8882.13 r270 top
C16 "GRM1555C1H2R4CA01D" 0402#1 1366.72,8882.13 r90 top
C17 "LLL185R71H222MA01L" 0306#1 598.91,8815.99 r270 bottom
C18 "LLL185R71H222MA01L" 0306#1 698.91,8815.99 r270 bottom
C19 "LLL185R71H222MA01L" 0306#1 984.09,8816.26 r270 bottom
C20 "LLL185R71H222MA01L" 0306#1 1099.09,8816.26 r270 bottom
C21 "LLL185R71E103MA01L" 0306#1 598.91,8815.99 r90 top
C22 "LLL185R71E103MA01L" 0306#1 698.91,8815.99 r90 top
C23 "LLL185R71E103MA01L" 0306#1 984.09,8816.26 r90 top
C24 "LLL185R71E103MA01L" 0306#1 1099.09,8816.26 r90 top
C25 "C1005X5R1A104K050BA" 0402#1 1284.09,8651.26 r0 top
C26 "C1608X5R1A105K080AC" 0603 1404.09,8756.26 r0 top
C27 "GRM155R71E103KA01D" 0402#1 1207.68,8729.28 r90 top
C28 "C1005X5R1A104K050BA" 0402#1 1539.09,8651.26 r0 top
C29 "TPSA106K010R0900" 3216-18 492.91,9299.99 r0 top
C30 "TPSA106K010R0900" 3216-18 895.09,9296.71 r180 top
C31 "C1005X5R1A104K050BA" 0402#1 497.91,9219.99 r0 top
C32 "C1005X5R1A104K050BA" 0402#1 497.91,9169.99 r0 top
C33 "C1005X5R1A104K050BA" 0402#1 895.09,9216.71 r180 top
C34 "C1005X5R1A104K050BA" 0402#1 895.09,9166.71 r180 top
C35 "GRM155R71E103KA01D" 0402#1 630.21,7703.86 r180 top
C36 "LLL185R71E103MA01L" 0306#1 600.71,7623.86 r270 top
C37 "LLL185R71E103MA01L" 0306#1 700.71,7623.86 r270 top
C38 "LLL185R71E103MA01L" 0306#1 985.89,7624.13 r270 top
C39 "LLL185R71E103MA01L" 0306#1 1100.89,7624.13 r270 top
C40 "LLL185R71H222MA01L" 0306#1 600.71,7623.86 r90 bottom
C41 "LLL185R71H222MA01L" 0306#1 700.71,7623.86 r90 bottom
C42 "LLL185R71H222MA01L" 0306#1 985.89,7624.13 r90 bottom
C43 "LLL185R71H222MA01L" 0306#1 1100.89,7624.13 r90 bottom
C44 "GRM1555C1H1R0CA01D" 0402#1 1268.52,7570.01 r90 top
C45 "GRM1555C1H2R4CA01D" 0402#1 1368.52,7570.01 r270 top
C46 "GRM155R71E103KA01D" 0402#1 1564.62,7509.68 r0 bottom
C47 "GRM155R71E103KA01D" 0402#1 365.71,7593.86 r315 top
C48 "GRM155R71E103KA01D" 0402#1 365.71,7418.86 r45 top
C49 "GRM1555C1H1R0CA01D" 0402#1 1268.52,7460.01 r270 top
C50 "GRM1555C1H2R4CA01D" 0402#1 1368.52,7460.01 r90 top
C51 "LLL185R71H222MA01L" 0306#1 600.71,7393.86 r270 bottom
C52 "LLL185R71H222MA01L" 0306#1 700.71,7393.86 r270 bottom
C53 "LLL185R71H222MA01L" 0306#1 985.89,7394.13 r270 bottom
C54 "LLL185R71H222MA01L" 0306#1 1100.89,7394.13 r270 bottom
C55 "LLL185R71E103MA01L" 0306#1 600.71,7393.86 r90 top
C56 "LLL185R71E103MA01L" 0306#1 700.71,7393.86 r90 top
C57 "LLL185R71E103MA01L" 0306#1 985.89,7394.13 r90 top
C58 "LLL185R71E103MA01L" 0306#1 1100.89,7394.13 r90 top
C59 "C1005X5R1A104K050BA" 0402#1 1285.89,7229.13 r0 top
C60 "C1608X5R1A105K080AC" 0603 1405.89,7334.13 r0 top
C61 "GRM155R71E103KA01D" 0402#1 1208.47,7302.75 r90 top
C62 "C1005X5R1A104K050BA" 0402#1 1540.89,7229.13 r0 top
C63 "TPSA106K010R0900" 3216-18 494.71,7877.86 r0 top
C64 "TPSA106K010R0900" 3216-18 896.89,7874.58 r180 top
C65 "C1005X5R1A104K050BA" 0402#1 499.71,7797.86 r0 top
C66 "C1005X5R1A104K050BA" 0402#1 499.71,7747.86 r0 top
C67 "C1005X5R1A104K050BA" 0402#1 896.89,7794.58 r180 top
C68 "C1005X5R1A104K050BA" 0402#1 896.89,7744.58 r180 top
C69 "C1005X7R1E104M050BB" 0402#1 5063.21,7346.18 r0 top
C70 "C1608X5R1A105K080AC" 0603 5061.21,7403.18 r180 top
C71 "GRM033C71A104KE14D" 0201_ADC 2647.99,8270.18 r0 top
C72 "GRM033C71A104KE14D" 0201_ADC 2648.99,8241.18 r0 top
C73 "GRM033C71A104KE14D" 0201_ADC 2647.99,8333.16 r0 top
C74 "C1005X7R1E104M050BB" 0402#1 4889.21,7154.18 r90 top
C75 "GRM033C71A104KE14D" 0201_ADC 2648.99,8304.17 r0 top
C76 "GRM033C71A104KE14D" 0201_ADC 2510.56,8474.92 r90 top
C77 "GRM033C71A104KE14D" 0201_ADC 2539.56,8475.92 r90 top
C78 "GRM033C71A104KE14D" 0201_ADC 2447.57,8474.92 r90 top
C79 "GRM033C71A104KE14D" 0201_ADC 2476.57,8475.92 r90 top
C80 "GRM033C71A104KE14D" 0201_ADC 2616.89,8271.59 r0 bottom
C81 "GRM033C71A104KE14D" 0201_ADC 2616.89,8241.6 r0 bottom
C82 "C1005X7R1E104M050BB" 0402#1 5286.21,7178.18 r180 top
C83 "C1005X7R1E104M050BB" 0402#1 5259.21,7102.18 r90 top
C84 "GRM033C71A104KE14D" 0201_ADC 2616.89,8334.58 r0 bottom
C85 "GRM033C71A104KE14D" 0201_ADC 2616.89,8304.59 r0 bottom
C86 "GRM033C71A104KE14D" 0201_ADC 2508.65,8443.99 r90 bottom
C87 "GRM033C71A104KE14D" 0201_ADC 2538.64,8443.99 r90 bottom
C88 "GRM033C71A104KE14D" 0201_ADC 2446.67,8443.99 r90 bottom
C89 "GRM033C71A104KE14D" 0201_ADC 2476.66,8443.99 r90 bottom
C90 "GRM155R71H472KA01D" 0402#1 2008.17,8268.62 r90 bottom
C91 "GRM155R71H472KA01D" 0402#1 1984.54,8245 r180 top
C92 "GRM155R71H472KA01D" 0402#1 2031.79,8245 r0 bottom
C93 "GRM155R71H472KA01D" 0402#1 2031.79,8205 r0 bottom
C94 "C1005X7R1E104M050BB" 0402#1 2103.89,8155.19 r270 top
C95 "C1005X7R1E104M050BB" 0402#1 2103.89,8048.19 r90 top
C96 "GRM033C71A104KE14D" 0201_ADC 2648.99,8178.19 r0 top
C97 "GRM155R71H472KA01D" 0402#1 1984.54,8205 r180 top
C98 "GRM033C71A104KE14D" 0201_ADC 2647.99,8207.19 r0 top
C99 "GRM155R71H472KA01D" 0402#1 2008.17,8181.38 r270 bottom
C100 "GRM033C71A104KE14D" 0201_ADC 2648.99,8115.2 r0 top
C101 "GRM033C71A104KE14D" 0201_ADC 2647.99,8144.2 r0 top
C102 "GRM033C71A104KE14D" 0201_ADC 2508.74,7974.27 r270 top
C103 "GRM033C71A104KE14D" 0201_ADC 2537.74,7975.27 r270 top
C104 "GRM033C71A104KE14D" 0201_ADC 2445.75,7974.27 r270 top
C105 "GRM033C71A104KE14D" 0201_ADC 2474.75,7975.27 r270 top
C106 "GRM033C71A104KE14D" 0201_ADC 2616.89,8178.61 r0 bottom
C107 "GRM1555C1H101JA01D" 0402#1 2840.1,9586.65 r90 top
C108 "293D106X0010B2TE3" 3528-21 2747.1,9626.65 r90 top
C109 "C1005X7R1E104M050BB" 0402#1 2890.1,9585.65 r90 top
C110 "GRM033C71A104KE14D" 0201_ADC 2616.89,8208.6 r0 bottom
C111 "GRM033C71A104KE14D" 0201_ADC 2616.89,8115.61 r0 bottom
C112 "GRM033C71A104KE14D" 0201_ADC 2616.89,8145.6 r0 bottom
C113 "GRM033C71A104KE14D" 0201_ADC 2509.16,8006.37 r270 bottom
C114 "GRM033C71A104KE14D" 0201_ADC 2539.15,8006.37 r270 bottom
C115 "GRM033C71A104KE14D" 0201_ADC 2446.17,8006.37 r270 bottom
C116 "GRM1555C1H101JA01D" 0402#1 2840.1,9458.65 r90 top
C117 "GRM1555C1H101JA01D" 0402#1 2890.1,9458.65 r90 top
C118 "GRM033C71A104KE14D" 0201_ADC 2476.16,8006.37 r270 bottom
C119 "293D106X0010B2TE3" 3528-21 2214.08,8593.9 r90 bottom
C120 "GRM033C71A104KE14D" 0201#1 2350.92,8101.87 r270 bottom
C121 "GRM033C71A104KE14D" 0201#1 2363.91,8398.32 r0 bottom
C122 "GRM033C71A104KE14D" 0201#1 2243.44,8146.35 r180 bottom
C123 "GRM033C71A104KE14D" 0201#1 2159.82,8304.79 r180 bottom
C124 "GRM033C71A104KE14D" 0201#1 2243.44,8303.83 r180 bottom
C125 "GRM033C71A104KE14D" 0201#1 2363.91,8146.35 r0 bottom
C126 "GRM033C71A104KE14D" 0201#1 2363.91,8177.85 r0 bottom
C127 "GRM033C71A104KE14D" 0201#1 2363.91,8209.35 r0 bottom
C128 "GRM033C71A104KE14D" 0201#1 2363.91,8240.84 r0 bottom
C129 "GRM033C71A104KE14D" 0201#1 2363.91,8272.34 r0 bottom
C130 "GRM033C71A104KE14D" 0201#1 2363.91,8303.83 r0 bottom
C131 "GRM033C71A104KE14D" 0201#1 2363.91,8335.33 r0 bottom
C132 "C1608X5R1A105K080AC" 0603 2370.27,8454.56 r0 bottom
C133 "C1608X5R1A105K080AC" 0603 2370.27,8516.56 r0 bottom
C134 "293D106X0010B2TE3" 3528-21 2308.91,7979.42 r0 bottom
C135 "GRM033C71A104KE14D" 0201#1 2319.43,8101.87 r270 bottom
C136 "GRM033C71A104KE14D" 0201#1 2243.44,8272.34 r180 bottom
C137 "GRM033C71A104KE14D" 0201#1 2243.44,8177.85 r180 bottom
C138 "GRM033C71A104KE14D" 0201#1 2306.43,8240.84 r180 bottom
C139 "GRM033C71A104KE14D" 0201#1 2306.43,8209.35 r180 bottom
C140 "GRM033C71A104KE14D" 0201#1 2237.27,8470.56 r180 bottom
C141 "GRM033C71A104KE14D" 0201#1 2160.82,8177.79 r180 bottom
C142 "GRM033C71A104KE14D" 0201#1 2159.82,8267.79 r180 bottom
C143 "GRM033C71A104KE14D" 0201#1 2170.27,8029.56 r180 bottom
C144 "GRM033C71A104KE14D" 0201#1 2170.27,7993.56 r180 bottom
C145 "GRM033C71A104KE14D" 0201#2 -233.43,10944.9 r180 bottom
C146 "GRM033C71A104KE14D" 0201#1 2237.27,8435.56 r180 bottom
C147 "CGA3E2X7R1H104K080AA" 0603 4127,5931 r180 bottom
C148 "C0603C104J3RACTU" 0603 4136,9169 r0 top
C149 "293D106X0010B2TE3" 3528-21 2791.87,7261.72 r0 bottom
C150 "GRM033C71A104KE14D" 0201#1 2508.4,8127.85 r90 bottom
C151 "GRM033C71A104KE14D" 0201#1 2476.91,8127.85 r90 bottom
C152 "GRM033C71A104KE14D" 0201#1 2476.91,8190.84 r90 bottom
C153 "GRM033C71A104KE14D" 0201#1 2508.4,8190.84 r90 bottom
C154 "GRM033C71A104KE14D" 0201#1 2642.39,8076 r0 bottom
C155 "GRM033C71A104KE14D" 0201#1 2476.91,8259.35 r270 bottom
C156 "GRM033C71A104KE14D" 0201#1 2508.4,8259.35 r270 bottom
C157 "GRM033C71A104KE14D" 0201#1 2476.91,8322.34 r270 bottom
C158 "GRM033C71A104KE14D" 0201#1 2508.4,8322.34 r270 bottom
C159 "C1608X5R1A105K080AC" 0603 2670.59,8027.35 r0 bottom
C160 "C1608X5R1A105K080AC" 0603 2670.59,7965.35 r0 bottom
C161 "GRM155R71E103KA01D" 0402#1 631.73,2779.63 r180 top
C162 "LLL185R71E103MA01L" 0306#1 602.23,2699.63 r270 top
C163 "LLL185R71E103MA01L" 0306#1 702.23,2699.63 r270 top
C164 "LLL185R71E103MA01L" 0306#1 987.41,2699.9 r270 top
C165 "LLL185R71E103MA01L" 0306#1 1102.41,2699.9 r270 top
C166 "LLL185R71H222MA01L" 0306#1 602.23,2699.63 r90 bottom
C167 "LLL185R71H222MA01L" 0306#1 702.23,2699.63 r90 bottom
C168 "LLL185R71H222MA01L" 0306#1 987.41,2699.9 r90 bottom
C169 "LLL185R71H222MA01L" 0306#1 1102.41,2699.9 r90 bottom
C170 "GRM1555C1H1R0CA01D" 0402#1 1270.04,2645.77 r90 top
C171 "GRM1555C1H2R4CA01D" 0402#1 1370.04,2645.77 r270 top
C172 "GRM155R71E103KA01D" 0402#1 1566.14,2585.45 r0 bottom
C173 "GRM155R71E103KA01D" 0402#1 367.23,2669.63 r315 top
C174 "GRM155R71E103KA01D" 0402#1 367.23,2494.63 r45 top
C175 "GRM1555C1H1R0CA01D" 0402#1 1270.04,2535.77 r270 top
C176 "GRM1555C1H2R4CA01D" 0402#1 1370.04,2535.77 r90 top
C177 "LLL185R71H222MA01L" 0306#1 602.23,2469.63 r270 bottom
C178 "LLL185R71H222MA01L" 0306#1 702.23,2469.63 r270 bottom
C179 "LLL185R71H222MA01L" 0306#1 987.41,2469.9 r270 bottom
C180 "LLL185R71H222MA01L" 0306#1 1102.41,2469.9 r270 bottom
C181 "LLL185R71E103MA01L" 0306#1 602.23,2469.63 r90 top
C182 "LLL185R71E103MA01L" 0306#1 702.23,2469.63 r90 top
C183 "LLL185R71E103MA01L" 0306#1 987.41,2469.9 r90 top
C184 "LLL185R71E103MA01L" 0306#1 1102.41,2469.9 r90 top
C185 "C1005X5R1A104K050BA" 0402#1 1287.41,2304.9 r0 top
C186 "C1608X5R1A105K080AC" 0603 1407.41,2409.9 r0 top
C187 "GRM155R71E103KA01D" 0402#1 1212.04,2380.59 r90 top
C188 "C1005X5R1A104K050BA" 0402#1 1542.41,2304.9 r0 top
C189 "TPSA106K010R0900" 3216-18 496.23,2953.63 r0 top
C190 "TPSA106K010R0900" 3216-18 898.41,2950.34 r180 top
C191 "C1005X5R1A104K050BA" 0402#1 501.23,2873.63 r0 top
C192 "C1005X5R1A104K050BA" 0402#1 501.23,2823.63 r0 top
C193 "C1005X5R1A104K050BA" 0402#1 898.41,2870.34 r180 top
C194 "C1005X5R1A104K050BA" 0402#1 898.41,2820.34 r180 top
C195 "GRM155R71E103KA01D" 0402#1 631.8,1360.29 r180 top
C196 "LLL185R71E103MA01L" 0306#1 602.3,1280.29 r270 top
C197 "LLL185R71E103MA01L" 0306#1 702.3,1280.29 r270 top
C198 "LLL185R71E103MA01L" 0306#1 987.48,1280.56 r270 top
C199 "LLL185R71E103MA01L" 0306#1 1102.48,1280.56 r270 top
C200 "LLL185R71H222MA01L" 0306#1 602.3,1280.29 r90 bottom
C201 "LLL185R71H222MA01L" 0306#1 702.3,1280.29 r90 bottom
C202 "LLL185R71H222MA01L" 0306#1 987.48,1280.56 r90 bottom
C203 "LLL185R71H222MA01L" 0306#1 1102.48,1280.56 r90 bottom
C204 "GRM1555C1H1R0CA01D" 0402#1 1270.11,1226.44 r90 top
C205 "GRM1555C1H2R4CA01D" 0402#1 1370.11,1226.44 r270 top
C206 "GRM155R71E103KA01D" 0402#1 1567.74,1163.94 r0 bottom
C207 "GRM155R71E103KA01D" 0402#1 367.3,1250.29 r315 top
C208 "GRM155R71E103KA01D" 0402#1 367.3,1075.29 r45 top
C209 "GRM1555C1H1R0CA01D" 0402#1 1270.11,1116.44 r270 top
C210 "GRM1555C1H2R4CA01D" 0402#1 1370.11,1116.44 r90 top
C211 "LLL185R71H222MA01L" 0306#1 602.3,1050.29 r270 bottom
C212 "LLL185R71H222MA01L" 0306#1 702.3,1050.29 r270 bottom
C213 "LLL185R71H222MA01L" 0306#1 987.48,1050.56 r270 bottom
C214 "LLL185R71H222MA01L" 0306#1 1102.48,1050.56 r270 bottom
C215 "LLL185R71E103MA01L" 0306#1 602.3,1050.29 r90 top
C216 "LLL185R71E103MA01L" 0306#1 702.3,1050.29 r90 top
C217 "LLL185R71E103MA01L" 0306#1 987.48,1050.56 r90 top
C218 "LLL185R71E103MA01L" 0306#1 1102.48,1050.56 r90 top
C219 "C1005X5R1A104K050BA" 0402#1 1287.48,885.56 r0 top
C220 "C1608X5R1A105K080AC" 0603 1407.48,990.56 r0 top
C221 "GRM155R71E103KA01D" 0402#1 1209.11,961.26 r90 top
C222 "C1005X5R1A104K050BA" 0402#1 1542.48,885.56 r0 top
C223 "TPSA106K010R0900" 3216-18 496.3,1534.29 r0 top
C224 "TPSA106K010R0900" 3216-18 898.48,1531.01 r180 top
C225 "C1005X5R1A104K050BA" 0402#1 501.3,1454.29 r0 top
C226 "C1005X5R1A104K050BA" 0402#1 501.3,1404.29 r0 top
C227 "C1005X5R1A104K050BA" 0402#1 898.48,1451.01 r180 top
C228 "C1005X5R1A104K050BA" 0402#1 898.48,1401.01 r180 top
C229 "C1005X7R1E104M050BB" 0402#1 5146.3,938.25 r0 top
C230 "C1608X5R1A105K080AC" 0603 5144.3,995.25 r180 top
C231 "GRM033C71A104KE14D" 0201_ADC 2651.32,1924.18 r0 top
C232 "GRM033C71A104KE14D" 0201_ADC 2652.32,1895.18 r0 top
C233 "GRM033C71A104KE14D" 0201_ADC 2651.32,1987.18 r0 top
C234 "C1005X7R1E104M050BB" 0402#1 4972.3,746.25 r90 top
C235 "GRM033C71A104KE14D" 0201_ADC 2652.32,1958.18 r0 top
C236 "GRM033C71A104KE14D" 0201_ADC 2513.89,2128.92 r90 top
C237 "GRM033C71A104KE14D" 0201_ADC 2541.89,2128.92 r90 top
C238 "GRM033C71A104KE14D" 0201_ADC 2450.9,2128.92 r90 top
C239 "GRM033C71A104KE14D" 0201_ADC 2479.9,2129.92 r90 top
C240 "GRM033C71A104KE14D" 0201_ADC 2620.22,1925.59 r0 bottom
C241 "GRM033C71A104KE14D" 0201_ADC 2620.22,1895.6 r0 bottom
C242 "C1005X7R1E104M050BB" 0402#1 5369.3,770.25 r180 top
C243 "C1005X7R1E104M050BB" 0402#1 5342.3,694.25 r90 top
C244 "GRM033C71A104KE14D" 0201_ADC 2620.22,1988.58 r0 bottom
C245 "GRM033C71A104KE14D" 0201_ADC 2620.22,1958.59 r0 bottom
C246 "GRM033C71A104KE14D" 0201_ADC 2511.98,2097.99 r90 bottom
C247 "GRM033C71A104KE14D" 0201_ADC 2541.97,2097.99 r90 bottom
C248 "GRM033C71A104KE14D" 0201_ADC 2450,2097.99 r90 bottom
C249 "GRM033C71A104KE14D" 0201_ADC 2479.99,2097.99 r90 bottom
C250 "GRM155R71H472KA01D" 0402#1 2011.5,1921.22 r90 bottom
C251 "GRM155R71H472KA01D" 0402#1 1987.88,1897.6 r180 top
C252 "GRM155R71H472KA01D" 0402#1 2035.12,1897.6 r0 bottom
C253 "GRM155R71H472KA01D" 0402#1 2035.12,1857.6 r0 bottom
C254 "C1005X7R1E104M050BB" 0402#1 2108.76,1809.37 r270 top
C255 "C1005X7R1E104M050BB" 0402#1 2108.76,1701.37 r90 top
C256 "GRM033C71A104KE14D" 0201_ADC 2652.32,1832.19 r0 top
C257 "GRM155R71H472KA01D" 0402#1 1987.88,1857.6 r180 top
C258 "GRM033C71A104KE14D" 0201_ADC 2651.32,1861.19 r0 top
C259 "GRM155R71H472KA01D" 0402#1 2011.5,1833.97 r270 bottom
C260 "GRM033C71A104KE14D" 0201_ADC 2652.32,1769.2 r0 top
C261 "GRM033C71A104KE14D" 0201_ADC 2651.32,1798.2 r0 top
C262 "GRM033C71A104KE14D" 0201_ADC 2512.07,1628.27 r270 top
C263 "GRM033C71A104KE14D" 0201_ADC 2541.07,1629.27 r270 top
C264 "GRM033C71A104KE14D" 0201_ADC 2449.08,1628.27 r270 top
C265 "GRM033C71A104KE14D" 0201_ADC 2478.08,1629.27 r270 top
C266 "GRM033C71A104KE14D" 0201_ADC 2620.22,1832.61 r0 bottom
C267 "GRM1555C1H101JA01D" 0402#1 2908.43,3240.88 r90 top
C268 "293D106X0010B2TE3" 3528-21 2815.43,3280.88 r90 top
C269 "C1005X7R1E104M050BB" 0402#1 2958.43,3239.88 r90 top
C270 "GRM033C71A104KE14D" 0201_ADC 2620.22,1862.6 r0 bottom
C271 "GRM033C71A104KE14D" 0201_ADC 2620.22,1769.62 r0 bottom
C272 "GRM033C71A104KE14D" 0201_ADC 2620.22,1799.61 r0 bottom
C273 "GRM033C71A104KE14D" 0201_ADC 2512.49,1660.37 r270 bottom
C274 "GRM033C71A104KE14D" 0201_ADC 2542.48,1660.37 r270 bottom
C275 "GRM033C71A104KE14D" 0201_ADC 2449.5,1660.37 r270 bottom
C276 "GRM1555C1H101JA01D" 0402#1 2908.43,3112.88 r90 top
C277 "GRM1555C1H101JA01D" 0402#1 2958.43,3112.88 r90 top
C278 "GRM033C71A104KE14D" 0201_ADC 2479.49,1660.37 r270 bottom
C279 "293D106X0010B2TE3" 3528-21 2208.02,2247.47 r90 bottom
C280 "GRM033C71A104KE14D" 0201#1 2354.25,1755.87 r270 bottom
C281 "GRM033C71A104KE14D" 0201#1 2367.24,2052.33 r0 bottom
C282 "GRM033C71A104KE14D" 0201#1 2246.77,1800.36 r180 bottom
C283 "GRM033C71A104KE14D" 0201#1 2163.15,1958.8 r180 bottom
C284 "GRM033C71A104KE14D" 0201#1 2246.77,1957.84 r180 bottom
C285 "GRM033C71A104KE14D" 0201#1 2367.24,1800.36 r0 bottom
C286 "GRM033C71A104KE14D" 0201#1 2367.24,1831.85 r0 bottom
C287 "GRM033C71A104KE14D" 0201#1 2367.24,1863.35 r0 bottom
